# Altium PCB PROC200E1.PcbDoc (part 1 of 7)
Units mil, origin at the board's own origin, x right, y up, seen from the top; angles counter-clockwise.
Board outline 4163.97 x 3505.34 mil, 6 copper layers (Top Layer, GND1, SIG1, PWR, GND2, Bottom), stack 58.132 mil thick; 367 components, 387 nets, 1784 pads, 858 vias.
Unrouted connection lines stored in the file: 17.
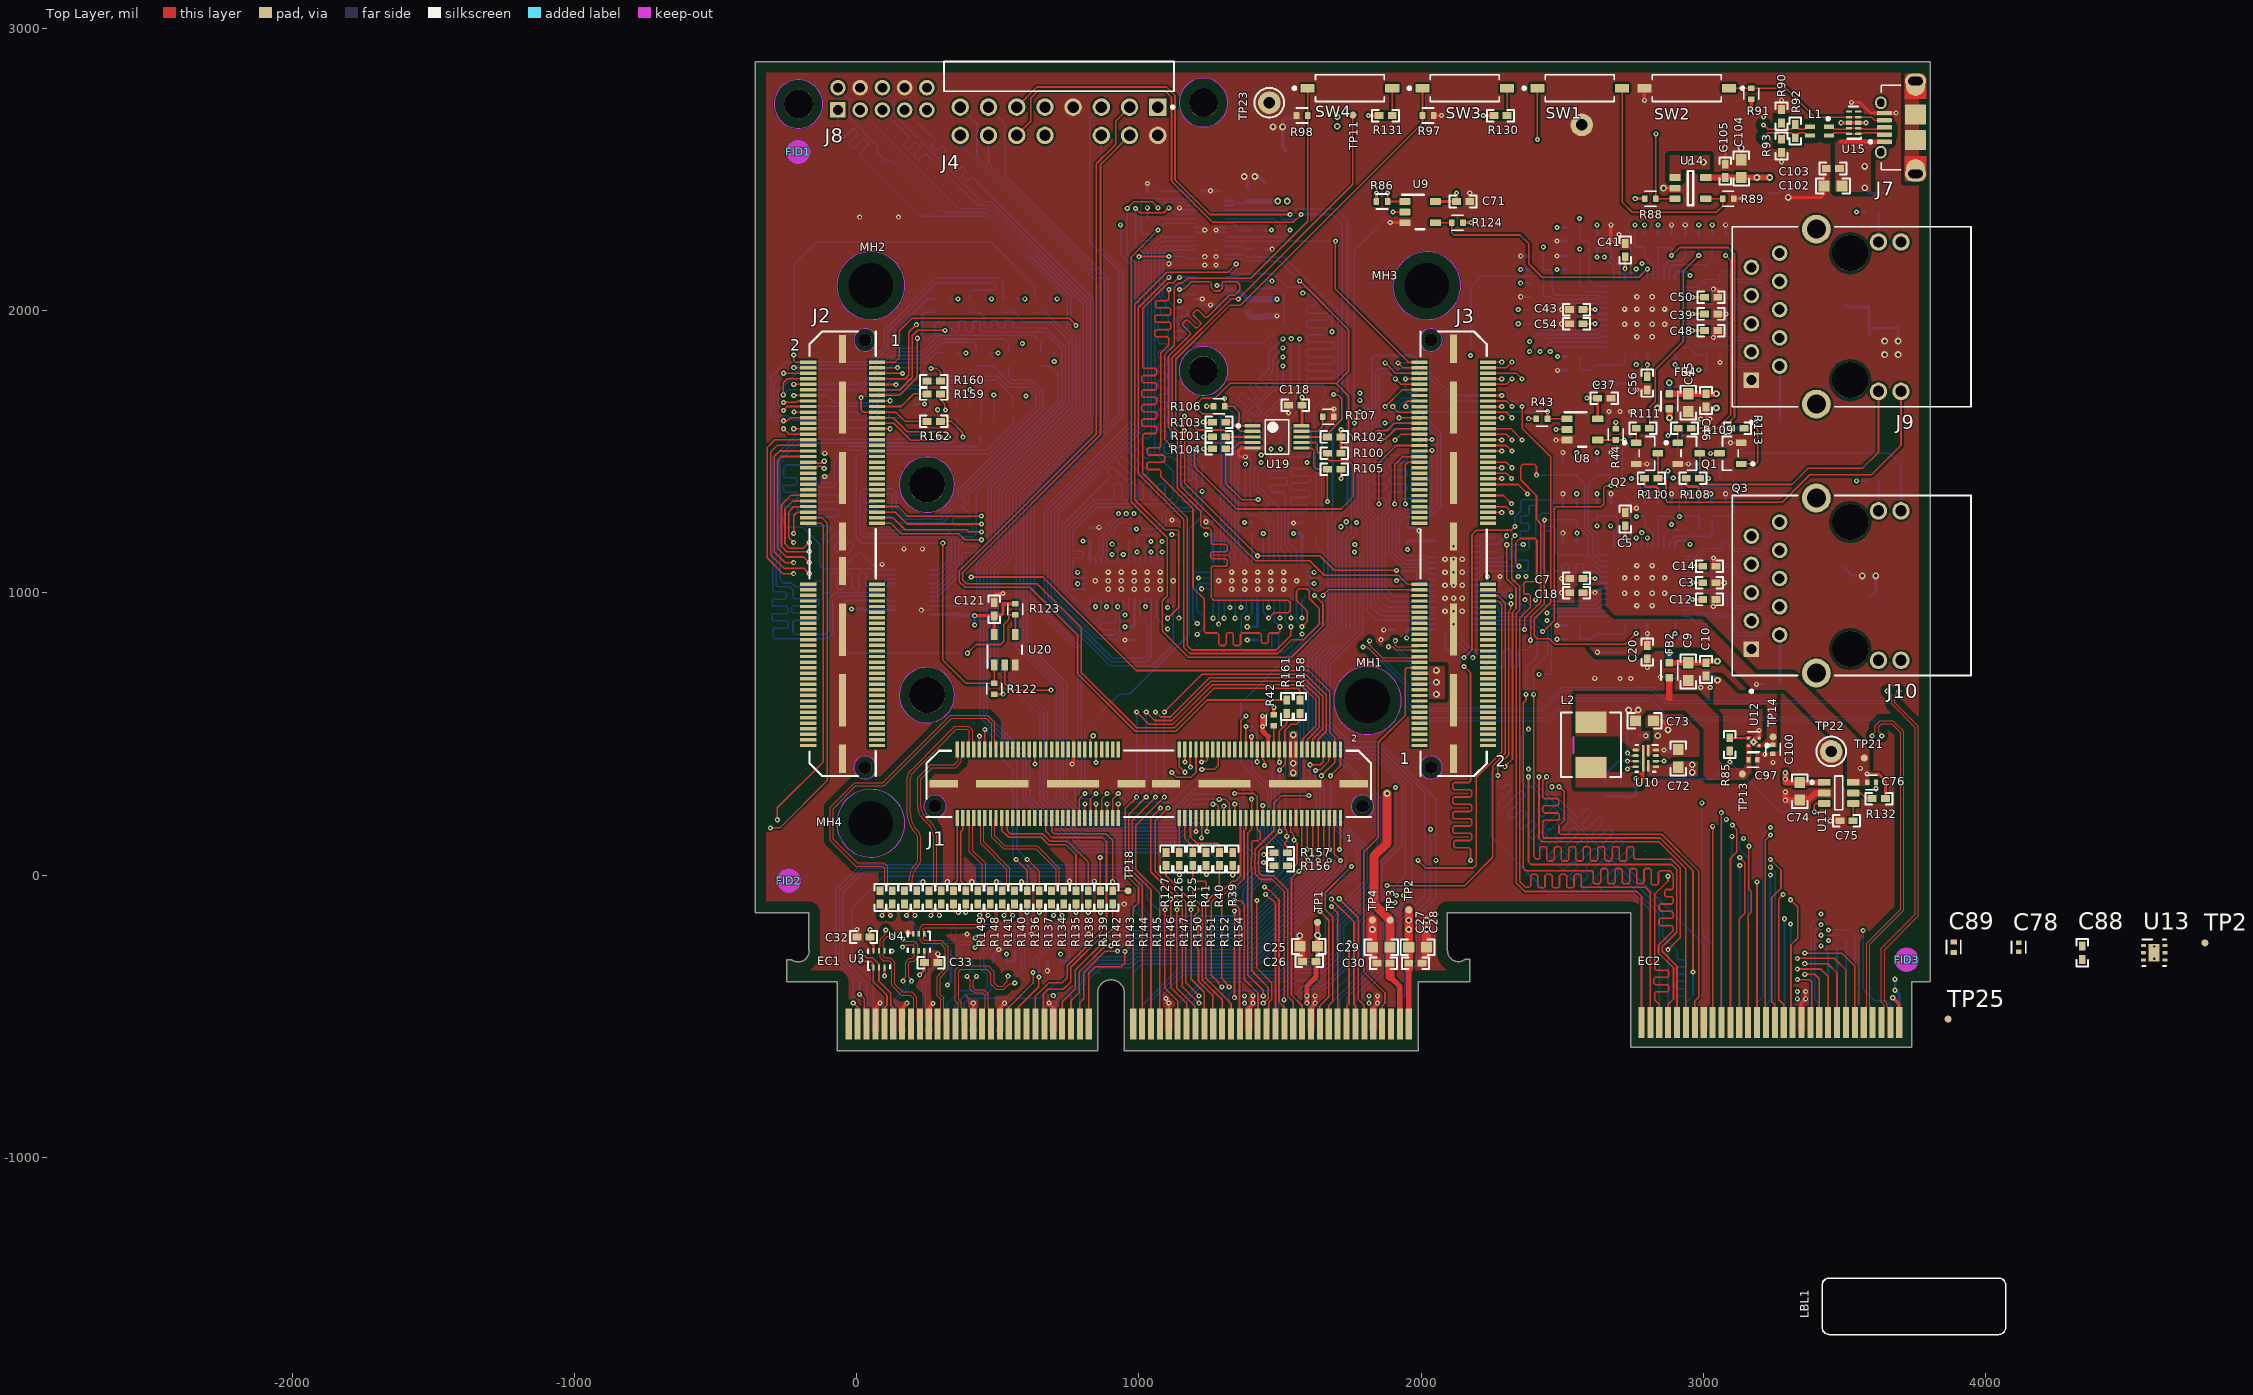
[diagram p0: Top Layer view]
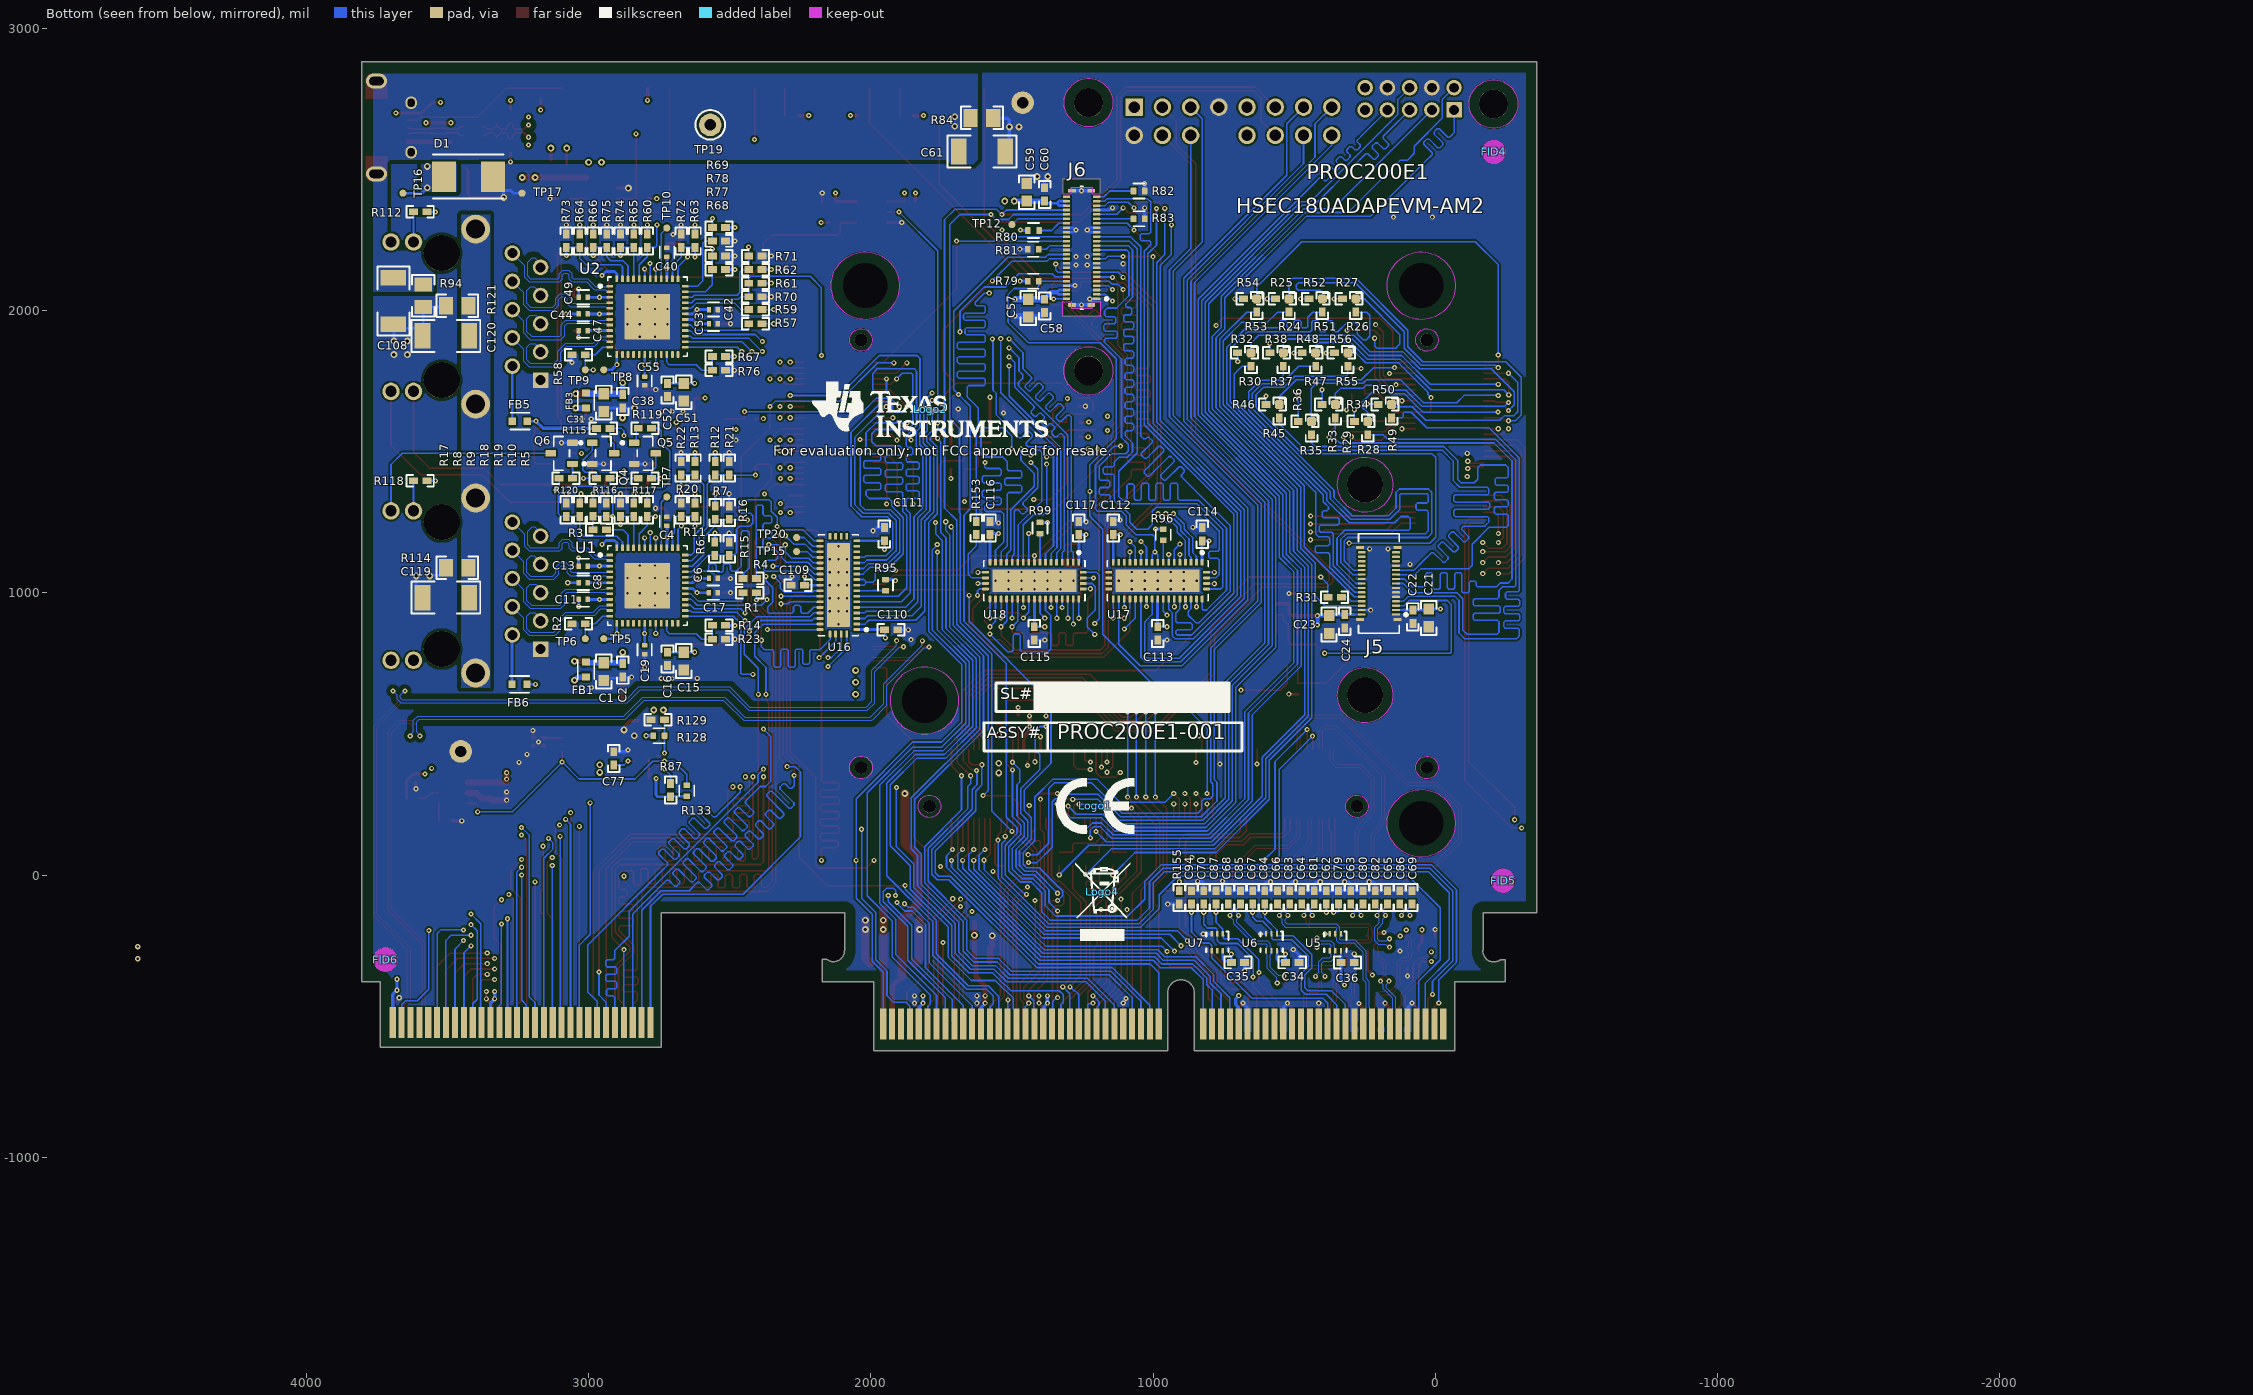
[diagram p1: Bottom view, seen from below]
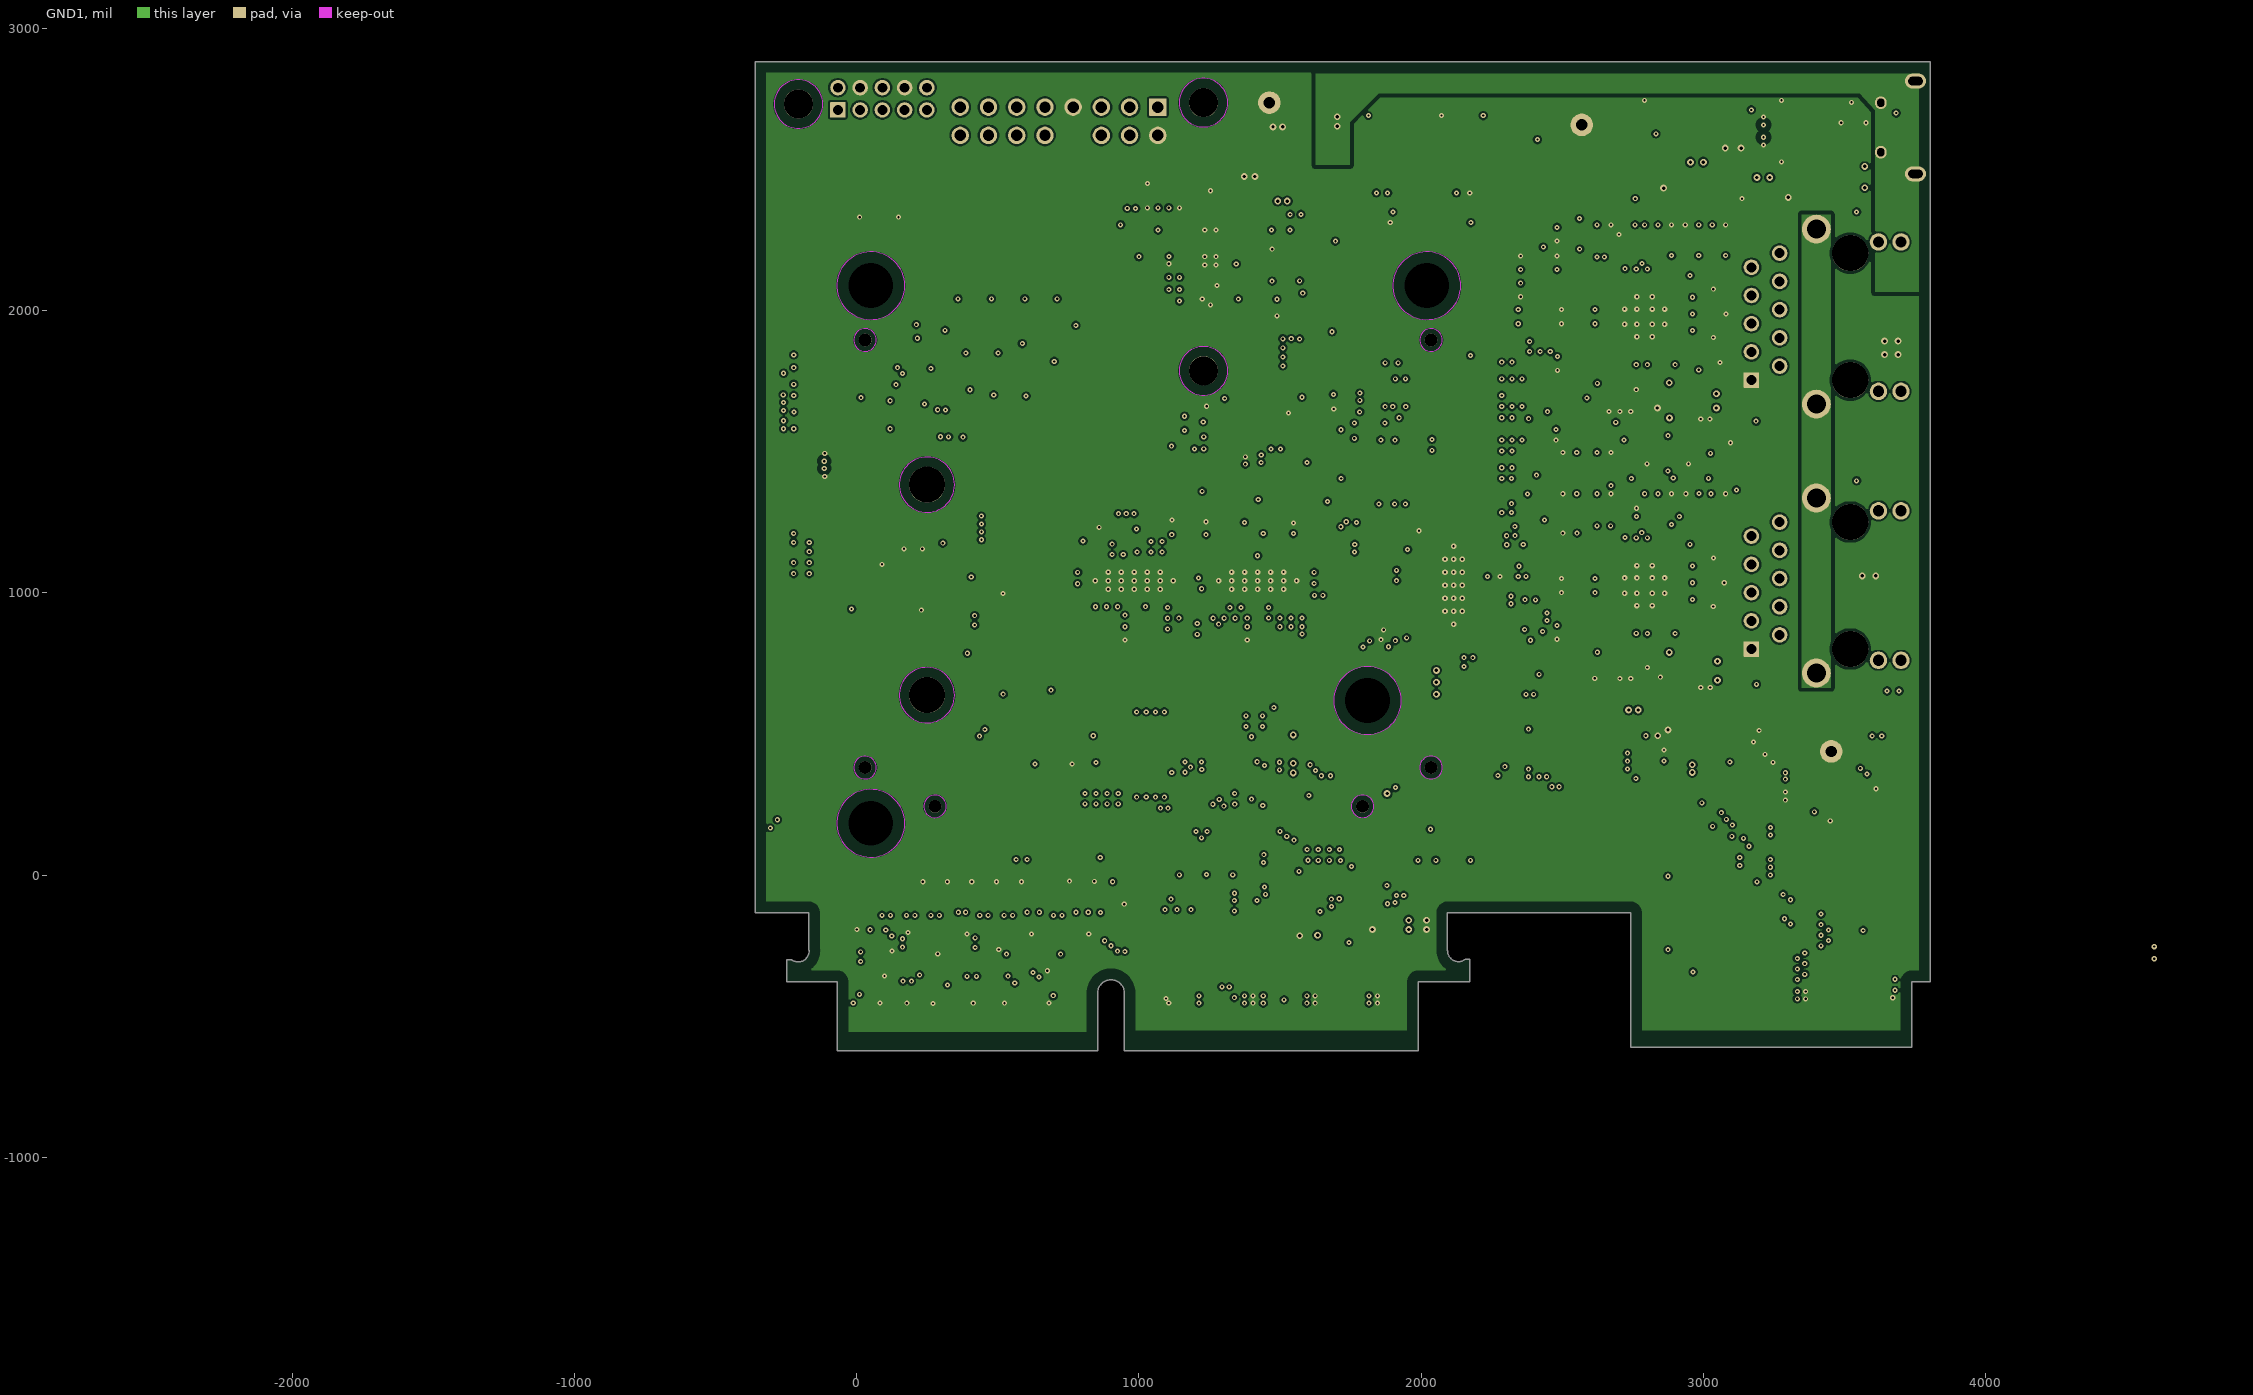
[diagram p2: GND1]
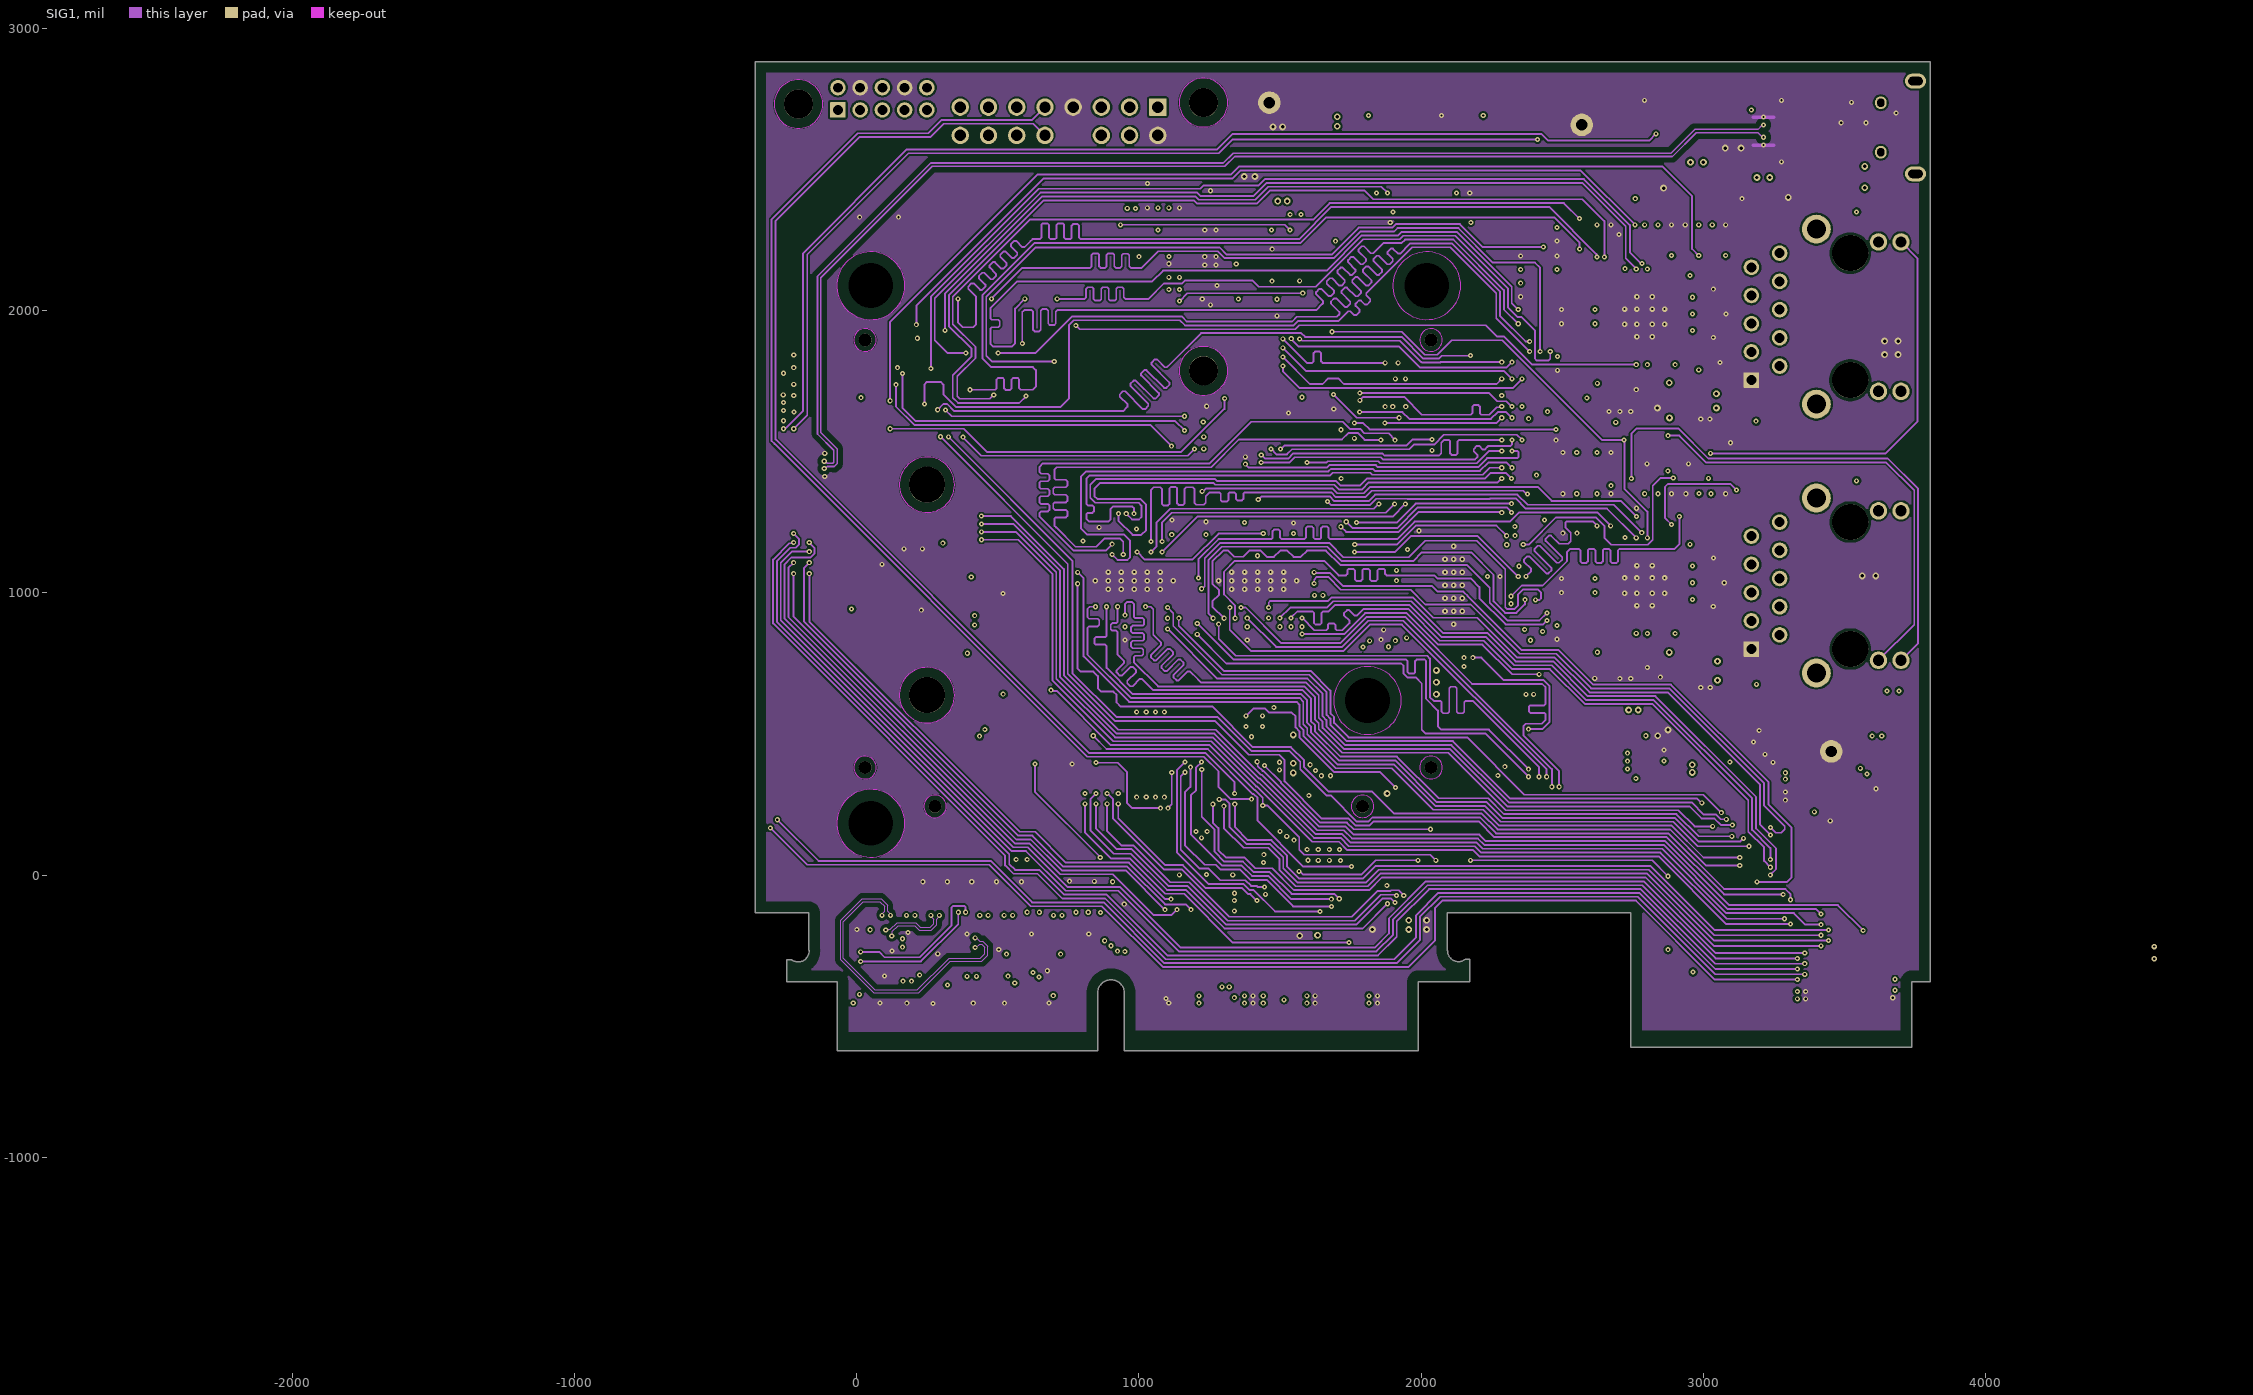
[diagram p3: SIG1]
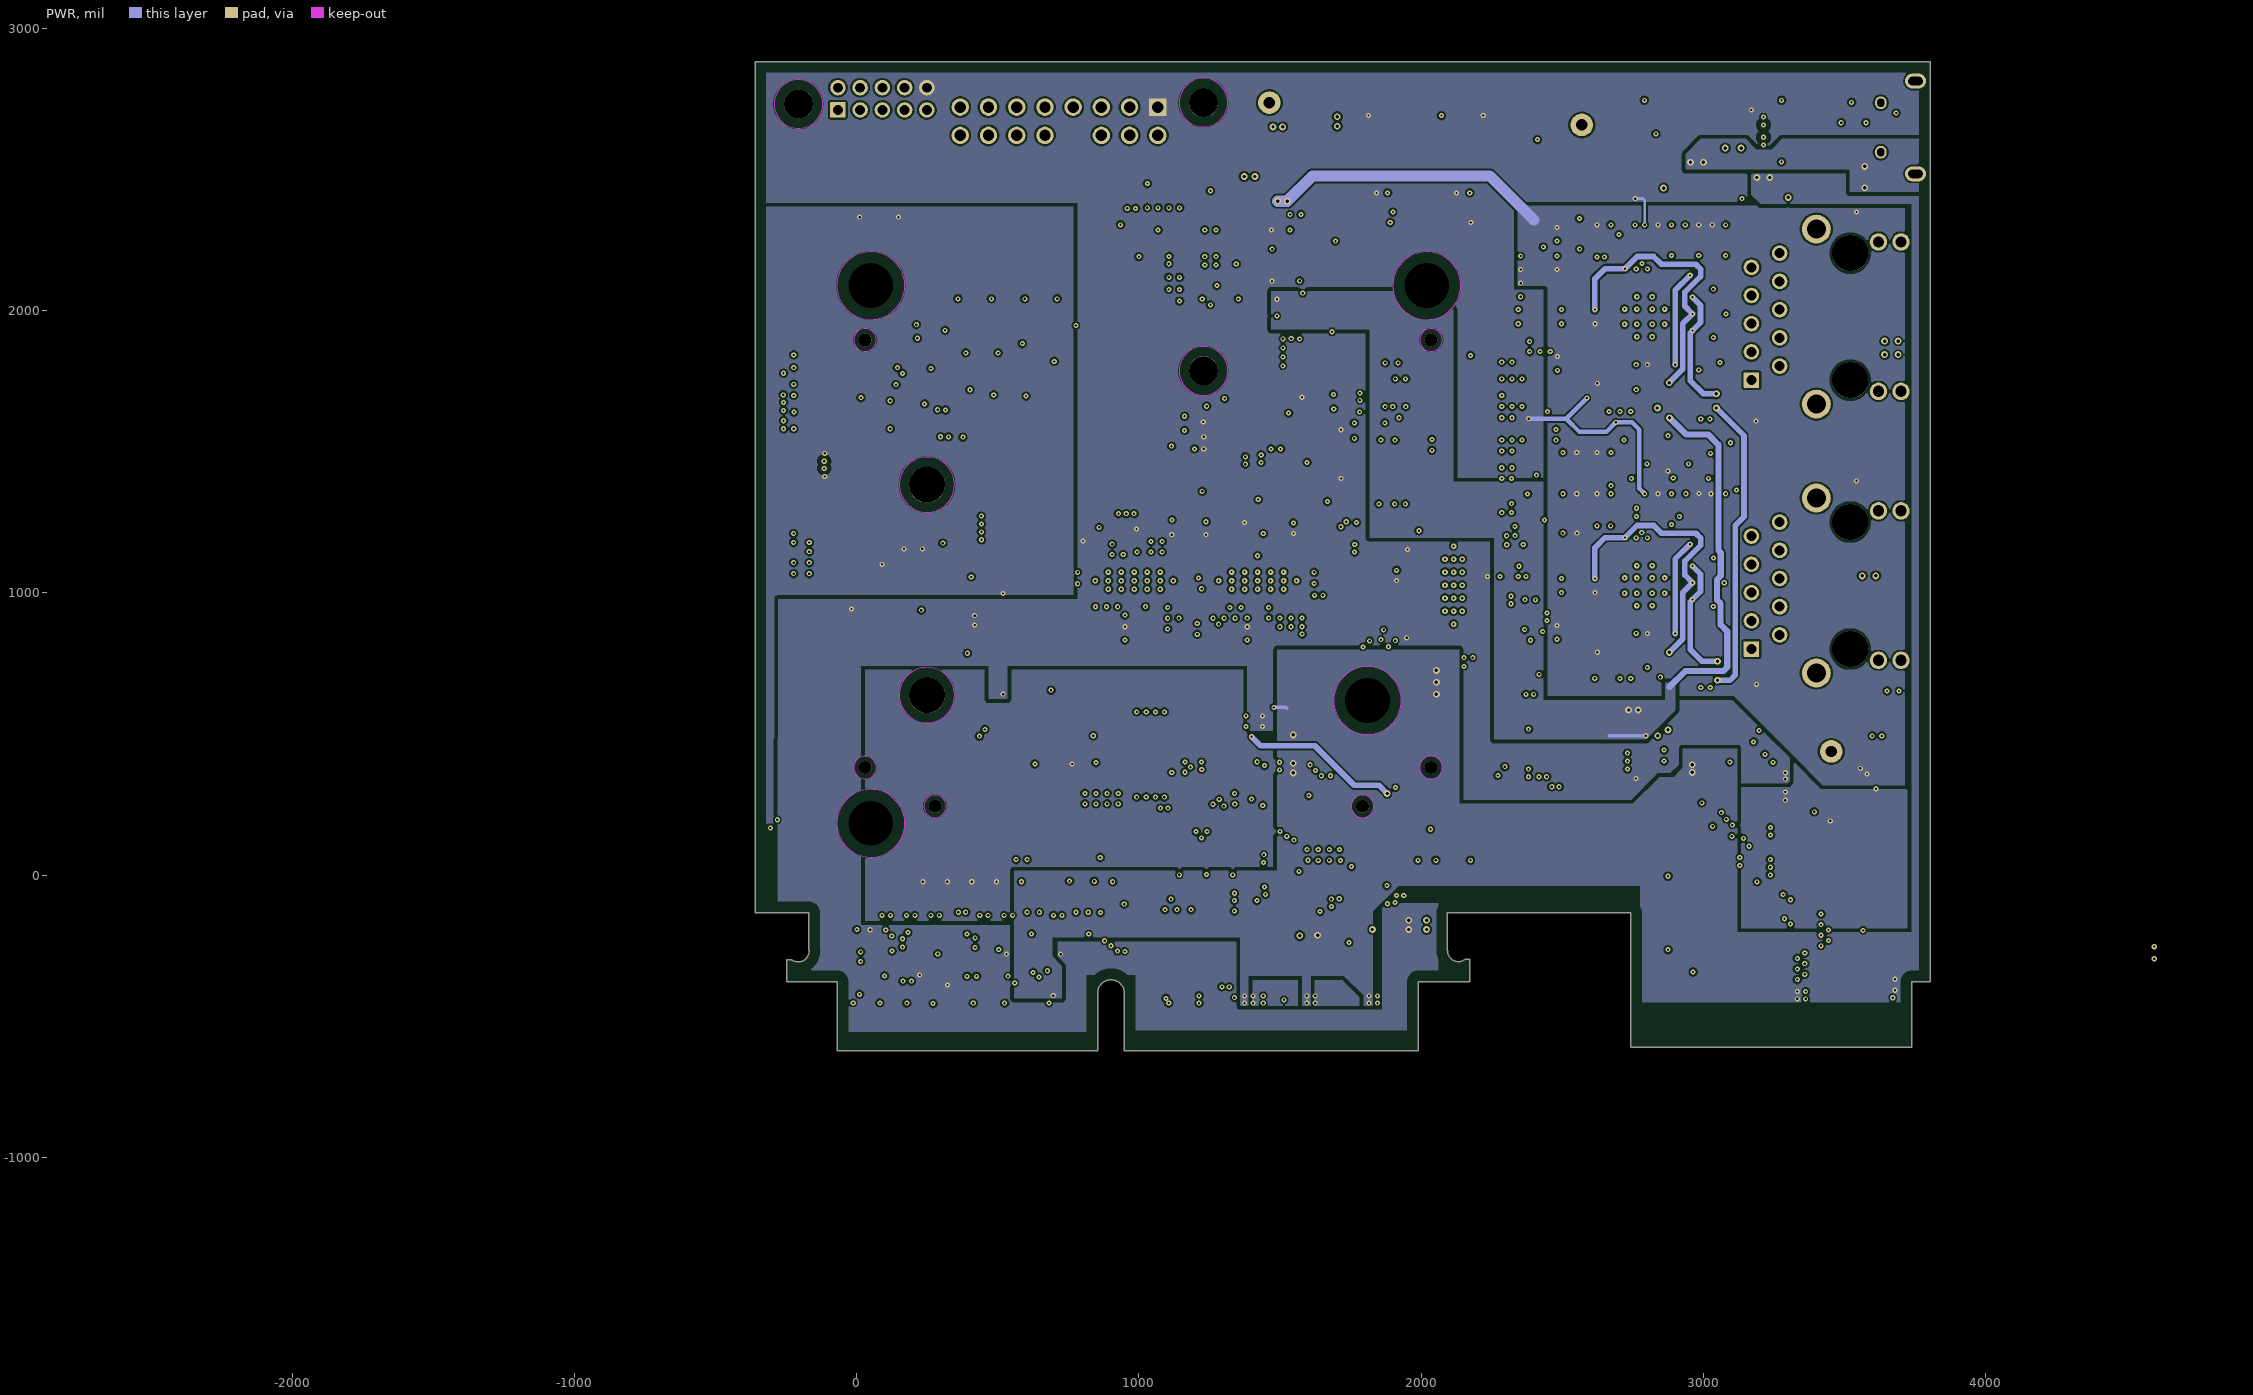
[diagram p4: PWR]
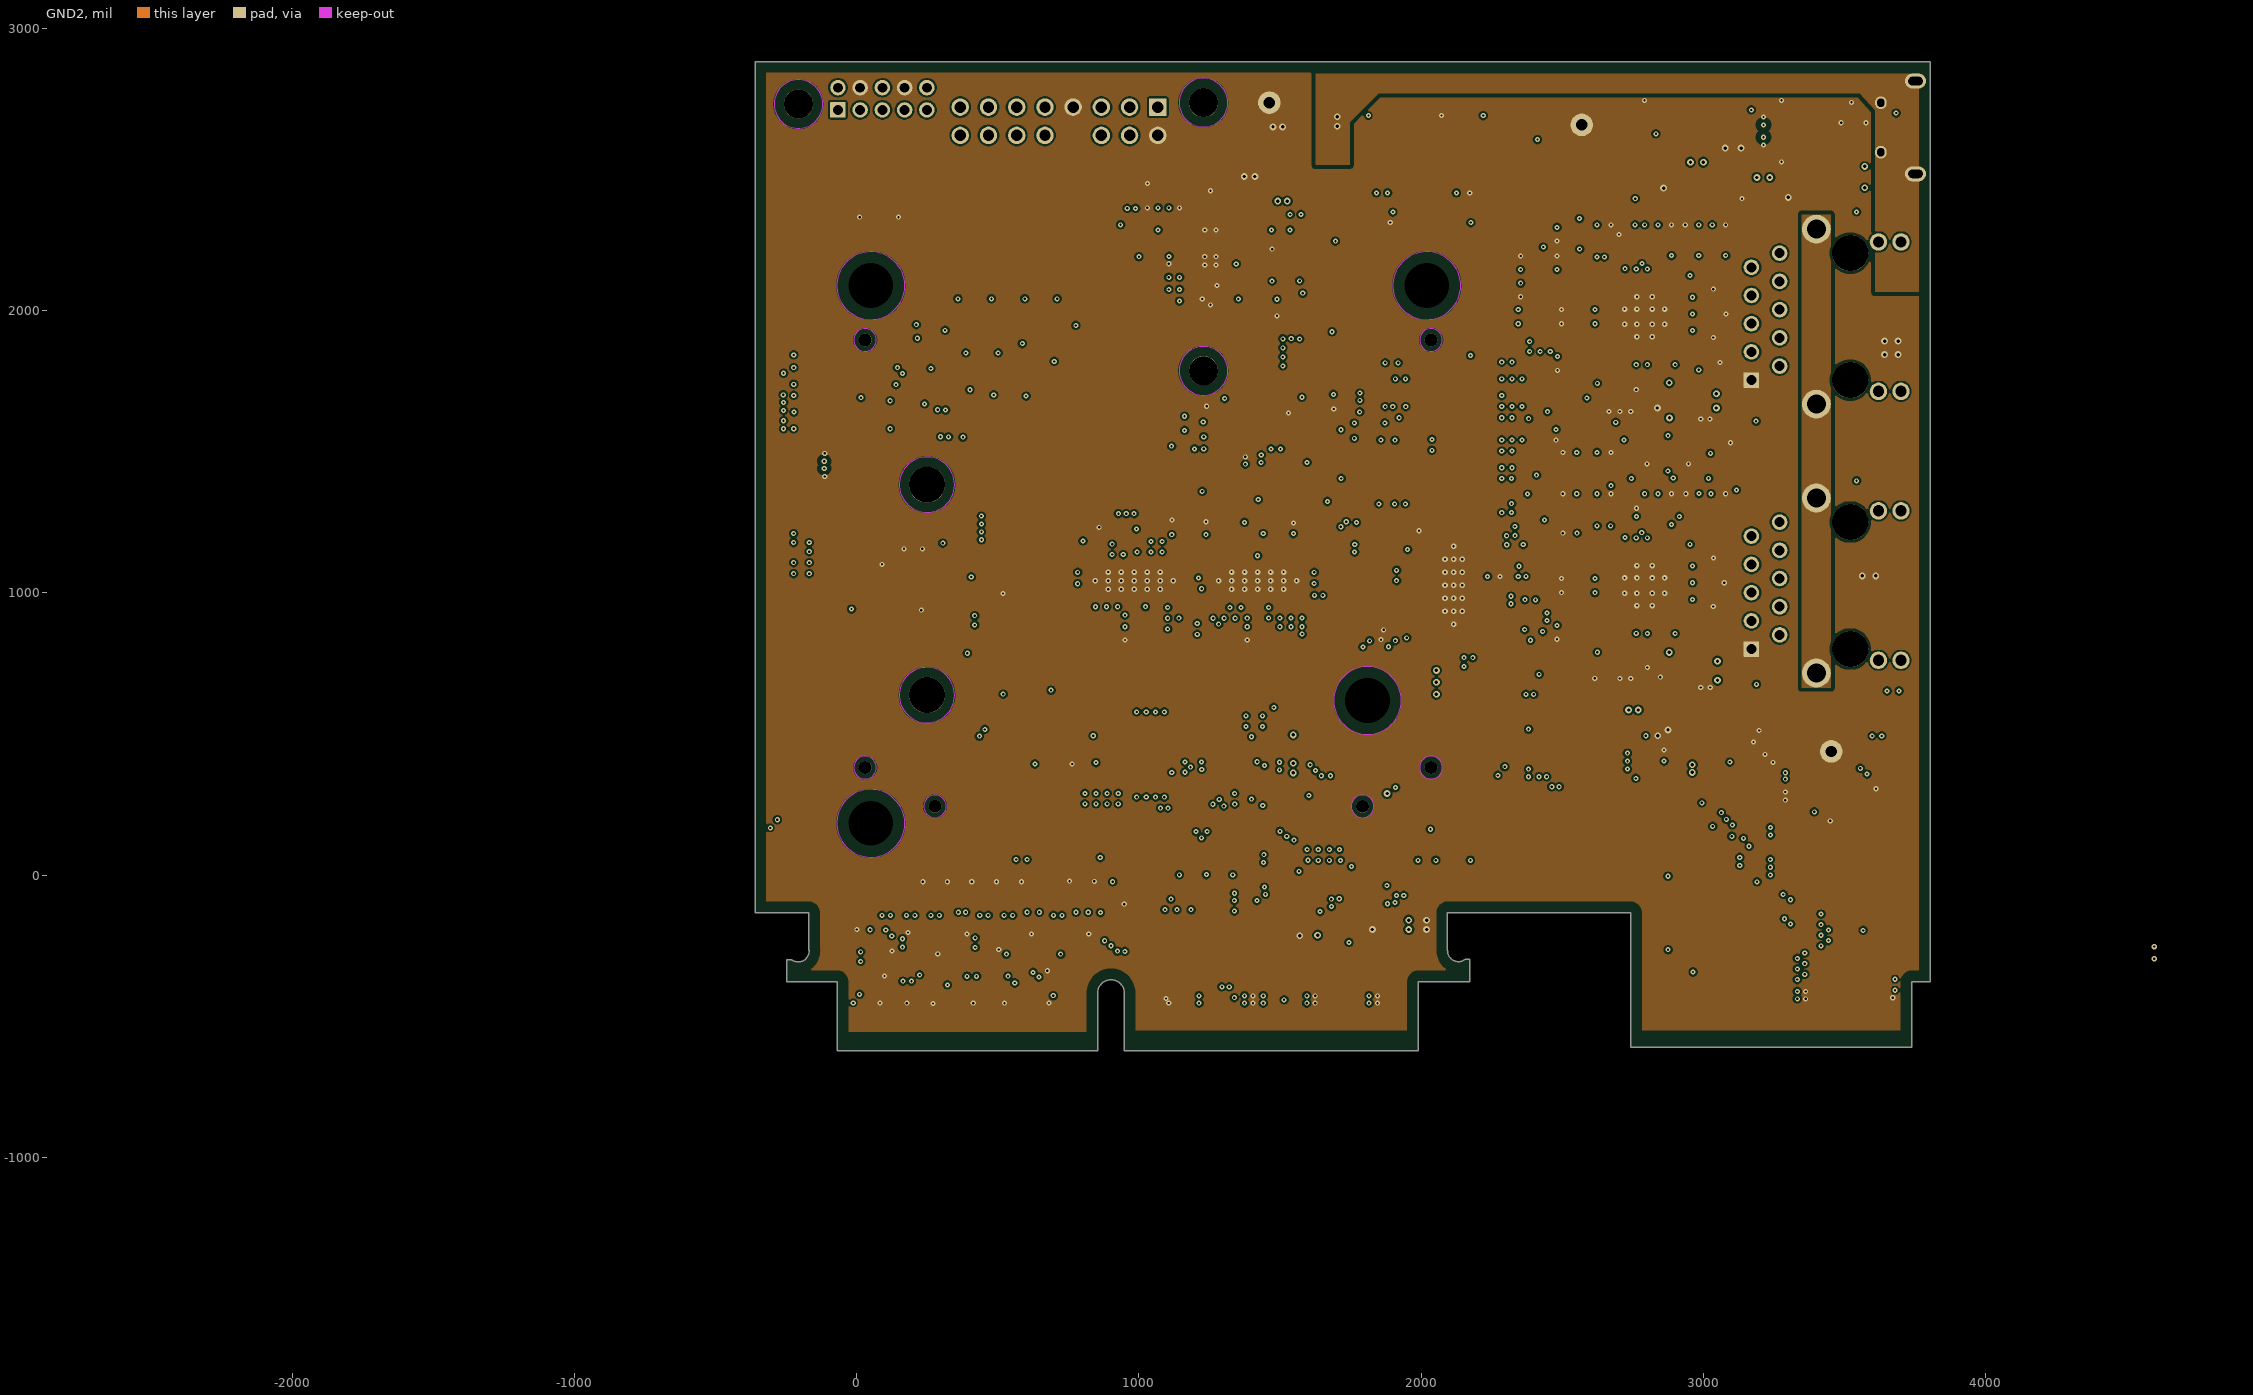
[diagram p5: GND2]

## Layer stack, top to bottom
Top Solder: solder mask 2, Solder Resist, Dk 3.6
Top Layer: signal copper 1.85
Dielectric 1: prepreg 3.696, FR-4, Dk 4.1
GND1: signal copper 1.26
Dielectric 2: core 5, FR-4, Dk 3.7
SIG1: signal copper 1.26
Dielectric 3: prepreg 32, FR-4, Dk 3.7
PWR: signal copper 1.26
Dielectric 4: core 5, FR-4, Dk 3.7
GND2: signal copper 1.26
Dielectric 5: prepreg 3.696, FR-4, Dk 4.1
Bottom: signal copper 1.85
Bottom Solder: solder mask 2, Solder Resist, Dk 3.6

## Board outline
853.8,-622.81 853.8,-418.09 853.9,-418.09 cw(c901.05,-418.09) 948.19,-418.09 948.29,-418.09 948.29,-622.81 1989.24,-622.81 1989.23,-377.97 2171.95,-377.97 2171.95,-298.97 2155.95,-298.97 cw(c2132.45,-267.85) 2093.45,-267.97 2092.95,-267.97 2092.95,-133.97 2743.26,-133.97 2743.26,-609.97 3738.54,-609.97 3738.54,-377.87 3803.95,-377.87 3803.95,2882.53 -360.02,2882.53 -360.02,-133.97 -169.05,-133.97 -169.05,-266.97 -168.55,-266.95 cw(c-207.5,-268.88) -231.05,-299.97 -247.05,-299.97 -247.05,-377.97 -68.64,-377.97 -68.64,-622.81

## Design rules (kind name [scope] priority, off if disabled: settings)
AcuteAngle [All] p1: minimum=4.50000000000000E+0001 checktracksonly=FALSE
AssemblyTestPointUsage [All] p1: valid=2
BoardOutlineClearance [All] p1: gap=40 ignorepadtopadclearanceinfootprint=FALSE
Clearance within_Diff_Pair [InAnyDifferentialPair and WithinRoom('Diff+Pair_Exception_USB_CONN')] p1: gap=4 ignorepadtopadclearanceinfootprint=FALSE except(18.66: Arc-Fill Arc-Poly Arc-Region Track-Fill Track-Poly Track-Region SMDPad-Fill SMDPad-Poly SMDPad-Region THPad-Fill THPad-Poly THPad-Region Via-Fill Via-Poly Via-Region Fill-Fill Fill-Poly Fill-Region Poly-Poly Poly-Region Region-Region)
Clearance Exception_Room [WithinRoom('Diff+Pair_Exception_J2_CONN')] p2: gap=4 ignorepadtopadclearanceinfootprint=FALSE except(15: Arc-Fill Arc-Poly Arc-Region Track-Fill Track-Poly Track-Region SMDPad-Fill SMDPad-Poly SMDPad-Region THPad-Fill THPad-Poly THPad-Region Via-Fill Via-Poly Via-Region Fill-Fill Fill-Poly Fill-Region Poly-Poly Poly-Region Region-Region)
Clearance Footprint_Exception [HasFootprint('DQN0004A-MFG')] p3: gap=4 ignorepadtopadclearanceinfootprint=FALSE except(0: Arc-Hole Track-Hole SMDPad-Hole THPad-Hole Via-Hole Fill-Hole Poly-Hole Region-Hole Text-Hole; 7: Arc-Fill Arc-Poly Track-Fill Track-Poly SMDPad-Fill SMDPad-Poly THPad-Fill THPad-Poly Via-Fill Via-Poly Fill-Fill Fill-Poly Fill-Text Poly-Poly Poly-Region Poly-Text Region-Text Text-Text)
Clearance 90E_3X_EXT [InDifferentialPairClass('DIFF_90E') vs InLayerClass('External Layer')] p4: gap=7 ignorepadtopadclearanceinfootprint=TRUE except(6: Arc-Arc Arc-Track Track-Track; 10: Arc-Hole Track-Hole SMDPad-Hole THPad-Hole Via-Hole Fill-Hole Poly-Hole Region-Hole Text-Hole; 12: Arc-Via Track-Via; 18.66: Arc-THPad Arc-Fill Arc-Poly Arc-Region Track-THPad Track-Fill Track-Poly Track-Region Via-Via Fill-Fill Fill-Poly Fill-Region Poly-Poly Poly-Region Region-Region)
Clearance 90E_3X_INT [InDifferentialPairClass('DIFF_90E') vs OnLayer('SIG1')] p5: gap=7 ignorepadtopadclearanceinfootprint=TRUE except(6: Arc-Arc Arc-Track Track-Track; 10: Arc-Hole Track-Hole SMDPad-Hole THPad-Hole Via-Hole Fill-Hole Poly-Hole Region-Hole Text-Hole; 12: Arc-Via Track-Via Via-Via; 19: Arc-Fill Arc-Poly Arc-Region Track-Fill Track-Poly Track-Region; 20: Arc-SMDPad Arc-THPad Track-SMDPad Track-THPad Fill-Fill Fill-Poly Fill-Region Poly-Poly Poly-Region Region-Region)
Clearance 100E_3X_EXT [InDifferentialPairClass('DIFF_100E') vs InLayerClass('External Layer')] p6: gap=7 ignorepadtopadclearanceinfootprint=TRUE except(6: Arc-Arc Arc-Track Arc-SMDPad Track-Track Track-SMDPad; 8: Arc-THPad Track-THPad; 10: Arc-Hole Track-Hole SMDPad-Hole THPad-Hole Via-Hole Fill-Hole Poly-Hole Region-Hole Text-Hole; 12: Arc-Via Arc-Fill Track-Via Track-Fill Via-Via; 21: Arc-Poly Arc-Region Track-Poly Track-Region Fill-Fill Fill-Poly Fill-Region Poly-Poly Poly-Region Region-Region)
Clearance 100E_3X_INT [InDifferentialPairClass('DIFF_100E') vs OnLayer('SIG1')] p7: gap=7 ignorepadtopadclearanceinfootprint=TRUE except(6: Arc-Arc Arc-Track Track-Track; 10: Arc-Hole Track-Hole SMDPad-Hole THPad-Hole Via-Hole Fill-Hole Poly-Hole Region-Hole Text-Hole; 12: Arc-Via Track-Via Via-Via; 18: Arc-SMDPad Arc-THPad Arc-Fill Arc-Poly Arc-Region Track-SMDPad Track-THPad Track-Fill Track-Poly Track-Region Fill-Fill Fill-Poly Fill-Region Poly-Poly Poly-Region Region-Region)
Clearance Clearance_Keepouts [IsKeepOut] p8: gap=0 ignorepadtopadclearanceinfootprint=FALSE
Clearance [All] p9: gap=7 ignorepadtopadclearanceinfootprint=TRUE except(5.8: Track-THPad; 6: Arc-SMDPad Arc-Via Track-SMDPad Track-Via; 6.6: Track-Track; 8: Via-Via; 10: Arc-Hole Track-Hole SMDPad-Hole THPad-Hole Via-Hole Fill-Hole Poly-Hole Region-Hole Text-Hole; 15: Fill-Fill Fill-Poly Fill-Region Poly-Poly)
ComponentClearance SOM_CONN [HasFootprint('SAMTEC_QTH-060-01-L-D-A') OR InComponentClass('TRIPAD_RES') OR HasFootprint('FP-DF40GB-48DP-0.4V(58)_HDR48-MFG')] p1: gap=0 collisioncheckmode=3 verticalgap=0 showdistances=FALSE
ComponentClearance [All] p2: gap=10 collisioncheckmode=3 verticalgap=10 showdistances=FALSE
DiffPairsRouting DiffPairsRouting_100OHM [InDifferentialPairClass('DIFF_100E')] p1: maxlimit=10 minlimit=6 mostfreqgap=10 toplayer_mingap=7 toplayer_maxgap=7 toplayer_prefgap=7 toplayer_minwidth=4 toplayer_maxwidth=4 toplayer_prefwidth=4 midlayer1_maxgap=6 midlayer1_prefgap=6 midlayer1_minwidth=4.2 midlayer1_maxwidth=4.2 midlayer1_prefwidth=4.2 midlayer4_maxgap=6 midlayer4_prefgap=6 midlayer4_minwidth=4.2 midlayer4_maxwidth=4.2 midlayer4_prefwidth=4.2 bottomlayer_mingap=7 bottomlayer_maxgap=7 bottomlayer_prefgap=7 bottomlayer_minwidth=4 bottomlayer_maxwidth=4 bottomlayer_prefwidth=4 impedanceprofiledriven=TRUE impedanceprofileid={A94D5FAB-CF00-4FEB-BD54-E9BDB7478A9D} impedanceprofilevalue=100.000000 maxuncoupledlength=600
DiffPairsRouting DiffPairsRouting_90OHM [InDifferentialPairClass('DIFF_90E')] p2: maxlimit=10 minlimit=6 mostfreqgap=10 toplayer_mingap=6.22 toplayer_maxgap=6.22 toplayer_prefgap=6.22 toplayer_minwidth=5 toplayer_maxwidth=5 toplayer_prefwidth=5 midlayer1_maxgap=6 midlayer1_prefgap=6 midlayer1_minwidth=5.7 midlayer1_maxwidth=5.7 midlayer1_prefwidth=5.7 midlayer4_maxgap=6 midlayer4_prefgap=6 midlayer4_minwidth=5.7 midlayer4_maxwidth=5.7 midlayer4_prefwidth=5.7 bottomlayer_mingap=6.22 bottomlayer_maxgap=6.22 bottomlayer_prefgap=6.22 bottomlayer_minwidth=5 bottomlayer_maxwidth=5 bottomlayer_prefwidth=5 impedanceprofiledriven=TRUE impedanceprofileid={C7C87971-DC9D-4F38-B813-0A1832E5FAEC} impedanceprofilevalue=90.000000 maxuncoupledlength=500
FabricationTestPointUsage TestPointUsage [All] p1: valid=2 allowmultiple=FALSE
FabricationTestpoint Testpoint [All] p1: side=3 testpointundercomponent=TRUE minsize=40 maxsize=100 preferedsize=60 minholesize=0 maxholesize=40 preferedholesize=32 testpointgrid=1 allowsidetop=TRUE allowsidebottom=TRUE usegrid=TRUE gridtolerance=0.01
FanoutControl Fanout_LCC [IsLCC] p1: bgadir=Out bgaviamode=Centered fanoutstyle=Auto fanoutdirection=Alternating viagrid=1 // Fanout_LCC (Default Rule)
FanoutControl Fanout_BGA [IsBGA] p2: bgadir=Out bgaviamode=Centered fanoutstyle=Auto fanoutdirection=Alternating viagrid=1 // Fanout_BGA (Default Rule)
FanoutControl Fanout_Default [All] p4: bgadir=Out bgaviamode=Centered fanoutstyle=Auto fanoutdirection=Alternating viagrid=1 // Fanout_Default (Default Rule)
FanoutControl Fanout_Small [(CompPinCount < 5)] p5: bgadir=Out bgaviamode=Centered fanoutstyle=Auto fanoutdirection=OutThenIn viagrid=1 // Fanout_Small (Default Rule)
Height Under_SOM [WithinRoom('SOM_HeightRestriction')] p1: minheight=0 maxheight=118.11 prefheight=78.74
Height [All] p2: minheight=0 maxheight=1000 prefheight=500
HoleSize [All] p1: absolutevalues=TRUE maxlimit=500 minlimit=7.87 maxpercent=80.000 minpercent=20.000
HoleToHoleClearance [All] p1: gap=9 allowstackedmicrovias=TRUE
MatchedLengths MII1_TX_GRP1 [InxSignalClass('MII1_TX_GRP1')] p1: tolerance=10 checknetsindiffpair=FALSE checkdiffpairvsdiffpair=TRUE checkxsignals=TRUE checkothers=TRUE
MatchedLengths MII1_TX_GRP2 [InxSignalClass('MII1_TX_GRP2')] p2: tolerance=10 checknetsindiffpair=FALSE checkdiffpairvsdiffpair=TRUE checkxsignals=TRUE checkothers=TRUE targetsourcename=ICSSM_MII1_TXCLK-NetR153_1_PP1
MatchedLengths MII1_RX_GRP1 [InxSignalClass('MII1_RX_GRP1')] p3: tolerance=10 checknetsindiffpair=FALSE checkdiffpairvsdiffpair=TRUE checkxsignals=TRUE checkothers=TRUE
MatchedLengths MII1_RX_GRP2 [InxSignalClass('MII1_RX_GRP2')] p4: tolerance=10 checknetsindiffpair=FALSE checkdiffpairvsdiffpair=TRUE checkxsignals=TRUE checkothers=TRUE targetsourcename=ICSSM_MII1_RXCLK_PP1
MatchedLengths FSI_HDR_RX [InxSignalClass('FSI_HDR_RX')] p5: tolerance=10 checknetsindiffpair=FALSE checkdiffpairvsdiffpair=TRUE checkxsignals=TRUE checkothers=TRUE
MatchedLengths FSI_HDR_TX [InxSignalClass('FSI_HDR_TX')] p6: tolerance=10 checknetsindiffpair=FALSE checkdiffpairvsdiffpair=TRUE checkxsignals=TRUE checkothers=TRUE targetsourcename=AM26x_FSITX0_CLK_PP1
MatchedLengths FSI_HSEC_RX [InxSignalClass('FSI_HSEC_RX')] p7: tolerance=10 checknetsindiffpair=FALSE checkdiffpairvsdiffpair=TRUE checkxsignals=TRUE checkothers=TRUE targetsourcename=AM26x_FSIRX0_CLK-HSEC_FSIRX0_CLK_PP1
MatchedLengths MII0_HSEC_RX_GRP1 [InxSignalClass('MII0_HSEC_RX_GRP1')] p8: tolerance=10 checknetsindiffpair=FALSE checkdiffpairvsdiffpair=TRUE checkxsignals=TRUE checkothers=TRUE
MatchedLengths MII0_HSEC_RX_GRP2 [InxSignalClass('MII0_HSEC_RX_GRP2')] p9: tolerance=10 checknetsindiffpair=FALSE checkdiffpairvsdiffpair=TRUE checkxsignals=TRUE checkothers=TRUE targetsourcename=HSEC_ICSSM_MII0_RXCLK_PP1
MatchedLengths MII0_HSEC_TX_GRP1 [InxSignalClass('MII0_HSEC_TX_GRP1')] p10: tolerance=10 checknetsindiffpair=FALSE checkdiffpairvsdiffpair=TRUE checkxsignals=TRUE checkothers=TRUE
MatchedLengths MII0_HSEC_TX_GRP2 [InxSignalClass('MII0_HSEC_TX_GRP2')] p11: tolerance=10 checknetsindiffpair=FALSE checkdiffpairvsdiffpair=TRUE checkxsignals=TRUE checkothers=TRUE targetsourcename=HSEC_ICSSM_MII0_TXCLK_PP1
MatchedLengths MII0_TX_GRP1 [InxSignalClass('MII0_TX_GRP1')] p12: tolerance=10 checknetsindiffpair=FALSE checkdiffpairvsdiffpair=TRUE checkxsignals=TRUE checkothers=TRUE
MatchedLengths MII0_TX_GRP2 [InxSignalClass('MII0_TX_GRP2')] p13: tolerance=10 checknetsindiffpair=FALSE checkdiffpairvsdiffpair=TRUE checkxsignals=TRUE checkothers=TRUE targetsourcename=ICSSM_MII0_TXCLK-R_ICSSM_MII0_TXCLK_PP1
MatchedLengths MII0_RX_GRP1 [InxSignalClass('MII0_RX_GRP1')] p14: tolerance=10 checknetsindiffpair=FALSE checkdiffpairvsdiffpair=TRUE checkxsignals=TRUE checkothers=TRUE
MatchedLengths MII0_RX_GRP2 [InxSignalClass('MII0_RX_GRP2')] p15: tolerance=10 checknetsindiffpair=FALSE checkdiffpairvsdiffpair=TRUE checkxsignals=TRUE checkothers=TRUE targetsourcename=ICSSM_MII0_RXCLK-R_ICSSM_MII0_RXCLK_PP1
MatchedLengths MII1_HSEC_TX_GRP1 [InxSignalClass('MII1_HSEC_TX_GRP1')] p16: tolerance=10 checknetsindiffpair=FALSE checkdiffpairvsdiffpair=TRUE checkxsignals=TRUE checkothers=TRUE
MatchedLengths MII1_HSEC_TX_GRP2 [InxSignalClass('MII1_HSEC_TX_GRP2')] p17: tolerance=10 checknetsindiffpair=FALSE checkdiffpairvsdiffpair=TRUE checkxsignals=TRUE checkothers=TRUE targetsourcename=HSEC_ICSSM_MII1_TXCLK_PP1
MatchedLengths MII1_HSEC_RX_GRP1 [InxSignalClass('MII1_HSEC_RX_GRP1')] p18: tolerance=10 checknetsindiffpair=FALSE checkdiffpairvsdiffpair=TRUE checkxsignals=TRUE checkothers=TRUE
MatchedLengths MII1_HSEC_RX_GRP2 [InxSignalClass('MII1_HSEC_RX_GRP2')] p19: tolerance=10 checknetsindiffpair=FALSE checkdiffpairvsdiffpair=TRUE checkxsignals=TRUE checkothers=TRUE targetsourcename=HSEC_ICSSM_MII1_RXCLK_PP1
MatchedLengths OSPI_Group [InxSignalClass('J2_OSPI_CONN')] p20: tolerance=10 checknetsindiffpair=FALSE checkdiffpairvsdiffpair=TRUE checkxsignals=TRUE checkothers=TRUE targetsourcename=CONN_OSPI1_CLK-RGMII1_RXC_PP1
MatchedLengths RGMII1_RX_GRP [InxSignalClass('J2_RGMII1_RX_GRP')] p21: tolerance=10 checknetsindiffpair=FALSE checkdiffpairvsdiffpair=TRUE checkxsignals=TRUE checkothers=TRUE
MatchedLengths RGMII1_TX_GRP [InxSignalClass('J2_RGMII1_TX_GRP')] p22: tolerance=10 checknetsindiffpair=FALSE checkdiffpairvsdiffpair=TRUE checkxsignals=TRUE checkothers=TRUE
MatchedLengths PHY1_GrpMatch [InxSignalClass('PHY1_U2')] p23: tolerance=10 checknetsindiffpair=FALSE checkdiffpairvsdiffpair=TRUE checkxsignals=TRUE checkothers=TRUE
MatchedLengths PHY2_GrpMatch [InxSignalClass('PHY2_U1')] p24: tolerance=10 checknetsindiffpair=FALSE checkdiffpairvsdiffpair=TRUE checkxsignals=TRUE checkothers=TRUE
MatchedLengths Diff_pairs [InAnyDifferentialPair] p25: tolerance=2 checknetsindiffpair=TRUE checkdiffpairvsdiffpair=FALSE checkxsignals=FALSE checkothers=FALSE
MinimumAnnularRing [All] p1: minimumring=5
MinimumSolderMaskSliver [All] p1: minsoldermaskwidth=6
PlaneClearance [All] p1: clearance=10
PlaneConnect [All] p1: planeconnectstyle=Direct reliefexpansion=10 reliefentries=4 reliefconductorwidth=10 reliefairgap=10
PolygonConnect [All] p1: connectstyle=Direct reliefconductorwidth=10 reliefentries=4 polygonreliefangle="90 Angle" airgapwidth=10
RoomDefinition Diff+Pair_Exception_J2_CONN [False vs False] p1: confinementstyle=ConfineIn formatcopy=TRUE lockcomponents=FALSE outline -319.67,1532.92 -74.89,1532.92 -74.89,1386.11 -319.67,1386.11
RoomDefinition Diff+Pair_Exception_USB_CONN [False vs False] p2: confinementstyle=ConfineIn formatcopy=TRUE lockcomponents=FALSE outline 3015,2855 3803.95,2855 3803.95,2386.29 3015,2386.29
RoomDefinition SOM_HeightRestriction [False vs False] p3: confinementstyle=ConfineIn formatcopy=TRUE lockcomponents=FALSE outline -360.02,2366.03 2750.22,2366.03 2750.22,-133.97 -360.02,-133.97
RoutingLayers [All] p1: top layer_v5=TRUE mid layer 1_v5=TRUE mid layer 2_v5=FALSE mid layer 3_v5=FALSE mid layer 4_v5=TRUE bottom layer_v5=TRUE
RoutingVias [All] p1: holewidth=8 width=22 viastyle="Through Hole" minholewidth=7.87 minwidth=18 maxholewidth=8 maxwidth=22 useviatemplates=TRUE viatemplateguid#1={BFC155CB-09EB-4870-8CCE-6FF5007BB52B} viatemplateguid#2={C4D4361A-8B44-4329-B568-289A0E0AE5F7} viatemplateguid#3={A6E074F1-B809-4F0C-AFE9-9FFF64B6E93D} viatemplatename#1=v46h20m0mx0(Tol8-8) viatemplatename#2=v50h20m50 viatemplatename#3=v61h30m0mx0(Tol8-8)
SilkToBoardRegionClearance [Not ((IsComment or IsDesignator) And (Hide <> 'False')) and not InRegion(1000,500,4000,800)] p1:
SilkToSilkClearance [All] p1: silktosilkclearance=4
SilkToSolderMaskClearance "Silk to Solder Mask Opening" [all] p1: minsilkscreentomaskgap=4 clearancetoexposedcopper=FALSE
SolderMaskExpansion [All] p1: expansion=1.97 istentingtop=FALSE
UnRoutedNet [All] p1: checkbadconnections=TRUE
Width Width_PWR [InNetClass('POWER')] p1: maxlimit=40 minlimit=7.89 preferedwidth=14
Width [InNetClass('All Nets')] p2: maxlimit=40 minlimit=5.66 preferedwidth=6.66 toplayer_maxwidth=10 toplayer_prefwidth=5.66 midlayer1_minwidth=6.66 midlayer1_maxwidth=10 midlayer2_minwidth=10 midlayer2_prefwidth=20 midlayer3_minwidth=10 midlayer3_prefwidth=20 midlayer4_minwidth=6.66 midlayer4_maxwidth=10 bottomlayer_maxwidth=10 bottomlayer_prefwidth=5.66 minimp=50.000000 maximp=50.000000 favimp=50.000000 checkconnectedcopper=TRUE
10 further rules are at their usual default settings.

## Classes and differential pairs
component class TRIPAD_RES: R24 R25 R26 R27 R28 R29 R30 R32 R33 R34 R35 R36 R37 R38 R45 R46 R47 R48 R49 R50 R51 R52 R53 R54 R55 R56
differential pair class DIFF_90E: AM26x_USB0 USBMICROAB
differential pair class HSEC_ADC: HSEC_ADC0_AIN_2_3 HSEC_ADC0_AIN_4_5 HSEC_ADC1_AIN_0_1 HSEC_ADC1_AIN_2_3 HSEC_ADC2_AIN_0_1 HSEC_ADC2_AIN_2_3
differential pair class DIFF_100E: AM26x_ADC0_AIN_2_3 AM26x_ADC0_AIN_4_5 AM26x_ADC1_AIN_0_1 AM26x_ADC1_AIN_2_3 AM26x_ADC2_AIN_0_1 AM26x_ADC2_AIN_2_3 HSEC_ADC0_AIN_2_3 HSEC_ADC0_AIN_4_5 HSEC_ADC1_AIN_0_1 HSEC_ADC1_AIN_2_3 HSEC_ADC2_AIN_0_1 HSEC_ADC2_AIN_2_3 PMIC_COMP1 PMIC_COMP2 RJ45_ETH1_D0 RJ45_ETH1_D1 RJ45_ETH1_D2 RJ45_ETH1_D3 RJ45_ETH2_D0 RJ45_ETH2_D1 RJ45_ETH2_D2 RJ45_ETH2_D3
differential pair class AM26x_ADC: AM26x_ADC0_AIN_2_3 AM26x_ADC0_AIN_4_5 AM26x_ADC1_AIN_0_1 AM26x_ADC1_AIN_2_3 AM26x_ADC2_AIN_0_1 AM26x_ADC2_AIN_2_3
differential pair class PMIC_COMP: PMIC_COMP1 PMIC_COMP2
differential pair class RJ45_ETH2: RJ45_ETH2_D0 RJ45_ETH2_D1 RJ45_ETH2_D2 RJ45_ETH2_D3
differential pair class RJ45_ETH1: RJ45_ETH1_D0 RJ45_ETH1_D1 RJ45_ETH1_D2 RJ45_ETH1_D3
net class POWER: 3V3_LDO2 5V0_LDO3 GND RJ45_1_VCC RJ45_2_VCC SHIELD2 SHIELD5 VBUS_MICRO_AB_5V0 VDD_ETH1_1V1_PHY VDD_ETH1_2V5_PHY VDD_ETH2_1V1_PHY VDD_ETH2_2V5_PHY VDD_ETH_1V1 VDD_ETH_2V5 VDDA1_1V8 VDDA2_1V8 VDDIO_3V3 VMAIN_5V0_IN
component class PROC200_RJ45_1_2: C119 C120 FB5 FB6 J9 J10 Q1 Q2 Q3 Q4 Q5 Q6 R108 R109 R110 R111 R112 R113 R114 R115 R116 R117 R118 R119 R120 R121
component class PROC200_PHY_MUX: C109 C110 C111 C112 C113 C114 C115 C116 C117 C118 R95 R96 R97 R98 R99 R100 R101 R102 R103 R104 R105 R106 R107 R130 R131 R153 SW3 SW4 TP15 TP20 U16 U17 U18 U19
component class "PROC200_OSPI_FSI _DAC_Emmulator_Header": C21 C22 C23 C24 C78 C88 C89 C121 J4 J5 J8 R24 R25 R26 R27 R28 R29 R30 R31 R32 R33 R34 R35 R36 R37 R38 R45 R46 R47 R48 R49 R50 R51 R52 R53 R54 R55 R56 R122 R123 TP24 U13 U20
component class PROC200_MII1_ADD_ON_CONN: C57 C58 C59 C60 C61 J6 R79 R80 R81 R82 R83 R84 TP11 TP12
component class PROC200_LDO_USB_MICRO-AB: C72 C73 C74 C75 C76 C77 C97 C100 C102 C103 C104 C105 C108 D1 J7 L1 L2 R85 R87 R88 R89 R90 R91 R92 R93 R94 R128 R129 R132 R133 SW1 SW2 TP13 TP14 TP16 TP17 TP21 TP22 TP23 U10 U11 U12 U14 U15
component class PROC200_High_Density_conn3: J3
component class PROC200_High_Density_conn1_2: J1 J2 R39 R40 R41 R42 R125 R126 R127 R156 R157 R158 R159 R160 R161 R162
component class PROC200_MII0_PHY2: C1 C2 C3 C4 C5 C6 C7 C8 C9 C10 C11 C12 C13 C14 C15 C16 C17 C18 C19 C20 C37 FB1 FB2 R1 R2 R3 R4 R5 R6 R7 R8 R9 R10 R11 R12 R13 R14 R15 R16 R17 R18 R19 R20 R21 R22 R23 R43 R44 TP5 TP6 TP7 U1 U8
component class PROC200_RGMII1_PHY1: C31 C38 C39 C40 C41 C42 C43 C44 C45 C46 C47 C48 C49 C50 C51 C52 C53 C54 C55 C56 C71 FB3 FB4 R57 R58 R59 R60 R61 R62 R63 R64 R65 R66 R67 R68 R69 R70 R71 R72 R73 R74 R75 R76 R77 R78 R86 R124 TP8 TP9 TP10 U2 U9
component class PROC200_HSEC_ADC: , C32 C33 C34 C35 C36 C62 C63 C64 C65 C66 C67 C68 C69 C70 C79 C80 C81 C82 C83 C84 C85 C86 C87 C94 R134 R135 R136 R137 R138 R139 R140 R141 R142 R143 R144 R145 R146 R147 R148 R149 R150 R151 R152 U3 U4 U5 U6 U7
component class PROC200_180pin_Edge_Connector: C25 C26 C27 C28 C29 C30 EC1 EC2 R154 R155 TP1 TP2 TP3 TP4 TP18 TP19 TP25
component class PROC200_EVM_Hardware: FID1 FID2 FID3 FID4 FID5 FID6 LBL1 Logo1 Logo2 Logo3 Logo4 MH1 MH2 MH3 MH4 ZZ1 ZZ2 ZZ3 ZZ4
differential pair PMIC_COMP2: +PMIC_COMP2_IN+ -PMIC_COMP2_IN-
differential pair PMIC_COMP1: +PMIC_COMP1_IN+ -PMIC_COMP1_IN-
differential pair USBMICROAB: +USBMICROAB_DP -USBMICROAB_DM
differential pair AM26x_USB0: +AM26x_USB0_DP -AM26x_USB0_DM
differential pair AM26x_ADC2_AIN_2_3: +AM26x_ADC2_AIN2_P -AM26x_ADC2_AIN3_N
differential pair AM26x_ADC2_AIN_0_1: +AM26x_ADC2_AIN0_P -AM26x_ADC2_AIN1_N
differential pair AM26x_ADC1_AIN_2_3: +AM26x_ADC1_AIN2_P -AM26x_ADC1_AIN3_N
differential pair AM26x_ADC1_AIN_0_1: +AM26x_ADC1_AIN0_P -AM26x_ADC1_AIN1_N
differential pair AM26x_ADC0_AIN_4_5: +AM26x_ADC0_AIN4_P -AM26x_ADC0_AIN5_N
differential pair AM26x_ADC0_AIN_2_3: +AM26x_ADC0_AIN2_P -AM26x_ADC0_AIN3_N
differential pair HSEC_ADC2_AIN_2_3: +HSEC_ADC2_AIN2_P -HSEC_ADC2_AIN3_N
differential pair HSEC_ADC2_AIN_0_1: +HSEC_ADC2_AIN0_P -HSEC_ADC2_AIN1_N
differential pair HSEC_ADC1_AIN_2_3: +HSEC_ADC1_AIN2_P -HSEC_ADC1_AIN3_N
differential pair HSEC_ADC1_AIN_0_1: +HSEC_ADC1_AIN0_P -HSEC_ADC1_AIN1_N
differential pair HSEC_ADC0_AIN_4_5: +HSEC_ADC0_AIN4_P -HSEC_ADC0_AIN5_N
differential pair HSEC_ADC0_AIN_2_3: +HSEC_ADC0_AIN2_P -HSEC_ADC0_AIN3_N
differential pair RJ45_ETH2_D3: +RJ45_ETH2_D3_P -RJ45_ETH2_D3_N
differential pair RJ45_ETH2_D2: +RJ45_ETH2_D2_P -RJ45_ETH2_D2_N
differential pair RJ45_ETH2_D1: +RJ45_ETH2_D1_P -RJ45_ETH2_D1_N
differential pair RJ45_ETH2_D0: +RJ45_ETH2_D0_P -RJ45_ETH2_D0_N
differential pair RJ45_ETH1_D3: +RJ45_ETH1_D3_P -RJ45_ETH1_D3_N
differential pair RJ45_ETH1_D2: +RJ45_ETH1_D2_P -RJ45_ETH1_D2_N
differential pair RJ45_ETH1_D1: +RJ45_ETH1_D1_P -RJ45_ETH1_D1_N
differential pair RJ45_ETH1_D0: +RJ45_ETH1_D0_P -RJ45_ETH1_D0_N

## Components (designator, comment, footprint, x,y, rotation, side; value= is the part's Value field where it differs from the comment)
C1 "GRM188C81C106MA73D" 0603 2945.8,720.94 r90 bottom value=10uF
C2 "GCM155R71E103KA37D" 0402 2879.3,725.86 r270 bottom value=0.01uF
C3 "GRM155R71E104KE14D" 0402 3021.23,1035.59 r0 top value=0.1uF
C4 "GRM155C81E105KE11D" FP-GRM155C81E105KE11D_0402-MFG 2722.6,1253.62 r90 bottom value=1µF
C5 "GRM155R71E104KE14D" 0402 2722.6,1261.49 r90 top value=0.1uF
C6 "GRM155C81E105KE11D" FP-GRM155C81E105KE11D_0402-MFG 2557.76,1050.91 r180 bottom value=1µF
C7 "GRM155R71E104KE14D" 0402 2549.91,1050.93 r180 top value=0.1uF
C8 "GRM155C81E105KE11D" FP-GRM155C81E105KE11D_0402-MFG 3019.35,1035.59 r0 bottom value=1µF
C9 "GRM188C81C106MA73D" 0603 2945.8,720.94 r90 top value=10uF
C10 "GCM155R71E103KA37D" 0402 3009.3,728.82 r270 top value=0.01uF
C11 "GRM155C81E105KE11D" FP-GRM155C81E105KE11D_0402-MFG 3019.35,976.53 r0 bottom value=1µF
C12 "GRM155R71E104KE14D" 0402 3021.23,976.53 r0 top value=0.1uF
C13 "GRM155C81E105KE11D" FP-GRM155C81E105KE11D_0402-MFG 3019.35,1094.64 r0 bottom value=1µF
C14 "GRM155R71E104KE14D" 0402 3021.23,1094.64 r0 top value=0.1uF
C15 "GRM188C81C106MA73D" 0603 2662.36,758.03 r90 bottom value=10uF
C16 "GCM155R71E103KA37D" 0402 2720.49,765.9 r270 bottom value=0.01uF
C17 "GRM155C81E105KE11D" FP-GRM155C81E105KE11D_0402-MFG 2557.81,1000.55 r180 bottom value=1µF
C18 "GRM155R71E104KE14D" 0402 2549.94,1000.55 r180 top value=0.1uF
C19 "GRM155C81E105KE11D" FP-GRM155C81E105KE11D_0402-MFG 2801.32,797.89 r270 bottom value=1µF
C20 "GRM155R71E104KE14D" 0402 2801.32,790.01 r270 top value=0.1uF
C21 "GRM188C81C106MA73D" 0603 23.23,911.12 r90 bottom value=10uF
C22 "GRM155R71E104KE14D" 0402 79.23,915.06 r270 bottom value=0.1uF
C23 "GRM188C81C106MA73D" 0603 376.49,887.5 r90 bottom value=10uF
C24 "GRM155R71E104KE14D" 0402 320.49,899.31 r270 bottom value=0.1uF
C25 "GRM188C81C106MA73D" 0603 1601.5,-253 r0 top value=10uF
C26 "GRM155R71E104KE14D" 0402 1603.38,-306 r180 top value=0.1uF
C27 "GRM188C81C106MA73D" 0603 1987.66,-256.16 r180 top value=10uF
C28 "GRM155R71E104KE14D" 0402 1979.79,-312.16 r0 top value=0.1uF
C29 "GRM188C81C106MA73D" 0603 1858.71,-256.22 r0 top value=10uF
C30 "GRM155R71E104KE14D" 0402 1866.59,-312.16 r180 top value=0.1uF
C31 "GRM188C81C106MA73D" 0603 2945.8,1673.7 r90 bottom value=10uF
C32 "GRM155R71E104KE14D" 0402 24,-219.5 r180 top value=0.1uF
C33 "GRM155R71E104KE14D" 0402 263.83,-310.04 r0 top value=0.1uF
C34 "GRM155R71E104KE14D" 0402 506.81,-309.7 r180 bottom value=0.1uF
C35 "GRM155R71E104KE14D" 0402 699.09,-309.7 r180 bottom value=0.1uF
C36 "GRM155R71E104KE14D" 0402 310.85,-309.81 r180 bottom value=0.1uF
C37 "GRM155R71E104KE14D" 0402 2648.73,1689.97 r180 top value=0.1uF
C38 "GCM155R71E103KA37D" 0402 2879.3,1678.62 r270 bottom value=0.01uF
C39 "GRM155R71E104KE14D" 0402 3027.14,1988.11 r0 top value=0.1uF
C40 "GRM155C81E105KE11D" FP-GRM155C81E105KE11D_0402-MFG 2722.6,2206.37 r90 bottom value=1µF
C41 "GRM155R71E104KE14D" 0402 2722.6,2214.25 r90 top value=0.1uF
C42 "GRM155C81E105KE11D" FP-GRM155C81E105KE11D_0402-MFG 2557.76,2003.66 r180 bottom value=1µF
C43 "GRM155R71E104KE14D" 0402 2549.89,2003.66 r180 top value=0.1uF
C44 "GRM155C81E105KE11D" FP-GRM155C81E105KE11D_0402-MFG 3019.35,1988.11 r0 bottom value=1µF
C45 "GRM188C81C106MA73D" 0603 2945.8,1673.7 r90 top value=10uF
C46 "GCM155R71E103KA37D" 0402 3009.3,1681.57 r270 top value=0.01uF
C47 "GRM155C81E105KE11D" FP-GRM155C81E105KE11D_0402-MFG 3019.35,1929.27 r0 bottom value=1µF
C48 "GRM155R71E104KE14D" 0402 3027.14,1929.27 r0 top value=0.1uF
C49 "GRM155C81E105KE11D" FP-GRM155C81E105KE11D_0402-MFG 3019.35,2047.4 r0 bottom value=1µF
C50 "GRM155R71E104KE14D" 0402 3027.14,2047.4 r0 top value=0.1uF
C51 "GRM188C81C106MA73D" 0603 2662.36,1710.78 r90 bottom value=10uF
C52 "GCM155R71E103KA37D" 0402 2720.49,1718.66 r270 bottom value=0.01uF
C53 "GRM155C81E105KE11D" FP-GRM155C81E105KE11D_0402-MFG 2557.76,1953.35 r180 bottom value=1µF
C54 "GRM155R71E104KE14D" 0402 2549.89,1953.35 r180 top value=0.1uF
C55 "GRM155C81E105KE11D" FP-GRM155C81E105KE11D_0402-MFG 2801.32,1750.64 r270 bottom value=1µF
C56 "GRM155R71E104KE14D" 0402 2801.32,1742.77 r270 top value=0.1uF
C57 "GRM188C81C106MA73D" 0603 1441.93,2008.73 r90 bottom value=10uF
C58 "GRM155R71E104KE14D" 0402 1384.45,2016.6 r270 bottom value=0.1uF
C59 "GRM188C81C106MA73D" 0603 1447.82,2419.38 r270 bottom value=10uF
C60 "GRM155R71E104KE14D" 0402 1384.45,2411.51 r90 bottom value=0.1uF
C61 "GR442QR73D102KW01L" 1808 1606.15,2563.73 r0 bottom value=1000pF
C62 "GRM1555C1H331JA01D" 0402 386,-79.38 r270 bottom value=330pF
C63 "GRM1555C1H331JA01D" 0402 299.38,-79.38 r270 bottom value=330pF
C64 "GRM1555C1H331JA01D" 0402 472.61,-79.38 r270 bottom value=330pF
C65 "GRM1555C1H331JA01D" 0402 169.46,-79.38 r270 bottom value=330pF
C66 "GRM1555C1H331JA01D" 0402 559.22,-79.38 r270 bottom value=330pF
C67 "GRM1555C1H331JA01D" 0402 647.18,-79.38 r270 bottom value=330pF
C68 "GRM1555C1H331JA01D" 0402 733.8,-79.38 r270 bottom value=330pF
C69 "GRM1555C1H331JA01D" 0402 82.85,-79.38 r270 bottom value=330pF
C70 "GRM1555C1H331JA01D" 0402 820.41,-79.38 r270 bottom value=330pF
C71 "GRM155R71E104KE14D" 0402 2148.62,2386.55 r180 top value=0.1uF
C72 "GRM188C81C106MA73D" 0603 2911,413.48 r270 top value=10uF
C73 "GRM188R60J226MEA0D" 0603 2791.5,546.48 r180 top value=22uF
C74 "GRM188C81C106MA73D" 0603 3341.94,296.91 r90 top value=10uF
C75 "GCM155R71E103KA37D" 0402 3507.03,192.19 r180 top value=0.01uF
C76 "GRM155C81E105KE11D" FP-GRM155C81E105KE11D_0402-MFG 3595.75,328.4 r0 top value=1µF
C77 "GCM155R71E103KA37D" 0402 2911.03,413.48 r90 bottom value=0.01uF
C78 "GRM155C81E105KE11D" FP-GRM155C81E105KE11D_0402-MFG 4117.11,-255.26 r90 top value=1µF
C79 "GRM1555C1H331JA01D" 0402 342.69,-79.38 r270 bottom value=330pF
C80 "GRM1555C1H331JA01D" 0402 256.07,-79.38 r270 bottom value=330pF
C81 "GRM1555C1H331JA01D" 0402 429.3,-79.38 r270 bottom value=330pF
C82 "GRM1555C1H331JA01D" 0402 212.77,-79.38 r270 bottom value=330pF
C83 "GRM1555C1H331JA01D" 0402 515.92,-79.38 r270 bottom value=330pF
C84 "GRM1555C1H331JA01D" 0402 603.87,-79.38 r270 bottom value=330pF
C85 "GRM1555C1H331JA01D" 0402 690.49,-79.38 r270 bottom value=330pF
C86 "GRM1555C1H331JA01D" 0402 126.15,-79.38 r270 bottom value=330pF
C87 "GRM1555C1H331JA01D" 0402 777.1,-79.38 r270 bottom value=330pF
C88 "GCM155R71E103KA37D" 0402 4342.11,-275.26 r90 top value=0.01uF
C89 "GRM155R61E225KE11D" "FP-GRM155R61E225KE11D_0402 (1005 metric)-MFG" 3887.11,-255.26 r90 top value=2.2µF
C94 "GRM1555C1H331JA01D" 0402 863.72,-79.38 r270 bottom value=330pF
C97 "GRM155C81E105KE11D" FP-GRM155C81E105KE11D_0402-MFG 3175.61,407.89 r0 top value=1µF
C100 "GRM155C81E105KE11D" FP-GRM155C81E105KE11D_0402-MFG 3246.36,445.38 r270 top value=1µF
C102 "GRM188C81C106MA73D" 0603 3459,2441.54 r0 top value=10uF
C103 "GRM155R71E104KE14D" 0402 3459,2503.54 r180 top value=0.1uF
C104 "GRM188C81C106MA73D" 0603 3133.66,2502.97 r270 top value=10uF
C105 "GRM155R71E104KE14D" 0402 3077.66,2495.09 r270 top value=0.1uF
C108 "GR442QR73D102KW01L" 1808 3691.49,2034.32 r90 bottom value=1000pF
C109 "GRM155R71E104KE14D" 0402 2258.68,1027.17 r0 bottom value=0.1uF
C110 "GRM155R71E104KE14D" 0402 1928.26,869.69 r180 bottom value=0.1uF
C111 "GRM155R71E104KE14D" 0402 1951.88,1208.27 r90 bottom value=0.1uF
C112 "GRM155R71E104KE14D" 0402 1141.24,1229.76 r90 bottom value=0.1uF
C113 "GRM155R71E104KE14D" 0402 983.76,856.32 r270 bottom value=0.1uF
C114 "GRM155R71E104KE14D" 0402 826.28,1207.64 r90 bottom value=0.1uF
C115 "GRM155R71E104KE14D" 0402 1420.43,856.32 r270 bottom value=0.1uF
C116 "GRM155R71E104KE14D" 0402 1577.91,1229.76 r90 bottom value=0.1uF
C117 "GRM155R71E104KE14D" 0402 1262.94,1229.76 r90 bottom value=0.1uF
C118 "GRM155R71E104KE14D" 0402 1553.85,1664.99 r180 top value=0.1uF
C119 "GR442QR73D102KW01L" 1808 3505.89,982.92 r180 bottom value=1000pF
C120 "GR442QR73D102KW01L" 1808 3505.89,1910.14 r180 bottom value=1000pF
C121 "GRM155R71E104KE14D" 0402 487.49,941.93 r270 top value=0.1uF
D1 "SMBJ6.5CA" SMB-Bi 3426,2475 r0 bottom value=6.5V
EC1 "controlCARD-120HSEC_Edge" controlCARD-120HSEC_Edge 901.05,-622.81 r0 top
EC2 "controlCARD-180HSEC-60pinAddon_Edge" controlCARD-180HSEC-60pinAddon_Edge 3237.32,-617.46 r0 top
FB1 "BLM18EG101TN1D" FP-BLM18EG101TN1D_0603-MFG 3009.3,728.82 r90 bottom
FB2 "BLM18EG101TN1D" FP-BLM18EG101TN1D_0603-MFG 2879.3,725.86 r90 top
FB3 "BLM18EG101TN1D" FP-BLM18EG101TN1D_0603-MFG 3009.3,1681.57 r90 bottom
FB4 "BLM18EG101TN1D" FP-BLM18EG101TN1D_0603-MFG 2879.3,1678.62 r90 top
FB5 "BLM18EG101TN1D" FP-BLM18EG101TN1D_0603-MFG 3243.71,1608.19 r0 bottom
FB6 "BLM18EG101TN1D" FP-BLM18EG101TN1D_0603-MFG 3244.91,675.92 r0 bottom
FID1 "Fiducial" Fiducial10-20 -207,2562 r90 top
FID2 "Fiducial" Fiducial10-20 -240,-20 r90 top
FID3 "Fiducial" Fiducial10-20 3720,-300 r90 top
FID4 "Fiducial" Fiducial10-20 -207,2562 r90 bottom
FID5 "Fiducial" Fiducial10-20 -240,-20 r90 bottom
FID6 "Fiducial" Fiducial10-20 3720,-300 r90 bottom
J1 "QTH-060-01-L-D-A" SAMTEC_QTH-060-01-L-D-A 1034.98,323.39 r180 top locked
J2 "QTH-060-01-L-D-A" SAMTEC_QTH-060-01-L-D-A -50.02,1138.39 r270 top locked
J3 "QTH-060-01-L-D-A" SAMTEC_QTH-060-01-L-D-A 2114.98,1138.19 r90 top locked
J4 "TSW-108-08-G-D-RA-008" FP-TSW-108-08-G-D-RA-008_HDR15-MFG 716.91,2829.97 r0 top
J5 "DF40GB(1.5)-30DS-0.4V(58)" FP-DF40GB(1.5)-30DS-0.4V(58)_HDR30-MFG 199.86,1033.17 r90 bottom locked
J6 "DF40GB-48DP-0.4V(58)" FP-DF40GB-48DP-0.4V(58)_HDR48-MFG 1253.28,2222.53 r90 bottom
J7 "629105150921" FP-629105150921_CONN_PTH_USB_8MM0_5MM6-MFG 3733.08,2648.85 r90 top
J8 "TMM-105-01-T-D" FP-TMM-105-01-T-D_HDR10-MFG 91,2750.37 r0 top
J9 "LPJG16314A4NL" FP-LPJG16314A4NL_CONN_RJ45-MFG 3525.21,1978.49 r90 top
J10 "LPJG16314A4NL" FP-LPJG16314A4NL_CONN_RJ45-MFG 3525.21,1025.74 r90 top
L1 "DLW21SN900HQ2L" IND_DLW21S 3411,2636.05 r270 top
L2 "IHLP2020BZER1R0M01" IHLP-2020BZ 2602,461.48 r90 top value=1uH
LBL1 "THT-14-423-10" Label_650x200 3746,-1528 r180 top
Logo1 "CE Mark" CE_Mark_5mm 1205,245 r180 bottom
Logo2 "Texas Instruments" TI_Stacked_Overlay_Small 1790,1650 r180 bottom
Logo3 "FCC disclaimer" FCC_disclaimer -290,-2170 r270 bottom
Logo4 "WEEE logo" WEEE_Minimum 1180,-60 r180 bottom
MH1 "MTG_NoPads" MTG_159mil 1809.98,618.39 r0 top
MH2 "MTG_NoPads" MTG_159mil 49.98,2088.39 r0 top
MH3 "MTG_NoPads" MTG_159mil 2019.98,2088.39 r0 top
MH4 "MTG_NoPads" MTG_159mil 49.98,183.39 r0 top
Q1 "BSS138LT1G" FP-BSS138LT1G_SOT-23-3-MFG 2948.05,1494.31 r0 top
Q2 "BSS138LT1G" FP-BSS138LT1G_SOT-23-3-MFG 2800.6,1494.31 r0 top
Q3 "BSS138LT1G" FP-BSS138LT1G_SOT-23-3-MFG 3095.49,1494.31 r180 top
Q4 "BSS138LT1G" FP-BSS138LT1G_SOT-23-3-MFG 2948.05,1494.31 r180 bottom
Q5 "BSS138LT1G" FP-BSS138LT1G_SOT-23-3-MFG 2800.6,1494.31 r180 bottom
Q6 "BSS138LT1G" FP-BSS138LT1G_SOT-23-3-MFG 3095.49,1494.31 r0 bottom
R1 "ERJ-2GE0R00X" 0402 2429.12,1000.6 r0 bottom value=0
R2 "CRCW040211K0FKED" 0402 3035.49,890.44 r0 bottom value=11.0k
R3 "ERJ-2GE0R00X" 0402 2960.81,1223.58 r0 bottom value=0
R4 "ERJ-2GE0R00X" 0402 2429.12,1050.91 r0 bottom value=0
R5 "CRCW04022K20FKED" 0402 2791.95,1294.45 r90 bottom value=2.20k
R6 "CRCW04022K49FKED" 0402 2552.49,1156.13 r90 bottom value=2.49k
R7 "CRCW04022K49FKED" 0402 2551.36,1284.45 r90 bottom value=2.49k
R8 "CRCW04022K49FKED" 0402 3031.24,1294.45 r90 bottom value=2.49k
R9 "CRCW04022K49FKED" 0402 2984.58,1295.05 r90 bottom value=2.49k
R10 "CRCW04022K49FKED" 0402 2839.49,1294.45 r90 bottom value=2.49k
R11 "CRCW04022K49FKED" 0402 2623.14,1294.45 r90 bottom value=2.49k
R12 "CRCW04022K49FKED" 0402 2551.36,1441.62 r90 bottom value=2.49k
R13 "CRCW04022K49FKED" 0402 2623.14,1441.62 r90 bottom value=2.49k
R14 "CRCW04022K49FKED" 0402 2538.05,884.54 r180 bottom value=2.49k
R15 "CRCW04022K49FKED" 0402 2501.95,1156.13 r270 bottom value=2.49k
R16 "CRCW04022K49FKED" 0402 2501.95,1284.45 r270 bottom value=2.49k
R17 "CRCW04022K49FKED" 0402 3079.03,1294.45 r270 bottom value=2.49k
R18 "CRCW04022K49FKED" 0402 2937.65,1294.45 r270 bottom value=2.49k
R19 "CRCW04022K49FKED" 0402 2887.03,1294.45 r270 bottom value=2.49k
R20 "CRCW04022K49FKED" 0402 2672.24,1294.45 r270 bottom value=2.49k
R21 "CRCW04022K49FKED" 0402 2501.95,1441.62 r270 bottom value=2.49k
R22 "CRCW04022K49FKED" 0402 2672.24,1441.62 r270 bottom value=2.49k
R23 "CRCW04022K49FKED" 0402 2538.05,835.44 r0 bottom value=2.49k
R24 "ERJ-2GE0R00X" 0402 518.51,2018.13 r270 bottom value=0
R25 "ERJ-2GE0R00X" 0402 542.13,2041.75 r0 bottom value=0
R26 "ERJ-2GE0R00X" 0402 281.66,2018.13 r270 bottom value=0
R27 "ERJ-2GE0R00X" 0402 305.28,2041.75 r0 bottom value=0
R28 "ERJ-2GE0R00X" 0402 239.54,1583.63 r270 bottom value=0
R29 "ERJ-2GE0R00X" 0402 263.16,1607.25 r0 bottom value=0
R30 "ERJ-2GE0R00X" 0402 653,1826.45 r270 bottom value=0
R31 "ERJ-2GE0R00X" 0402 356.65,984.18 r0 bottom value=0
R32 "ERJ-2GE0R00X" 0402 676.62,1850.07 r0 bottom value=0
R33 "ERJ-2GE0R00X" 0402 354.02,1643.63 r270 bottom value=0
R34 "ERJ-2GE0R00X" 0402 377.65,1667.25 r0 bottom value=0
R35 "ERJ-2GE0R00X" 0402 438.51,1583.63 r270 bottom value=0
R36 "ERJ-2GE0R00X" 0402 462.13,1607.25 r0 bottom value=0
R37 "ERJ-2GE0R00X" 0402 538.51,1826.45 r270 bottom value=0
R38 "ERJ-2GE0R00X" 0402 562.13,1850.07 r0 bottom value=0
R39 "ERJ-2GE0R00X" 0402 1332.54,56.87 r90 top value=0
R40 "ERJ-2GE0R00X" 0402 1285.23,56.87 r90 top value=0
R41 "ERJ-2GE0R00X" 0402 1237.92,56.87 r90 top value=0
R42 "RC0402JR-0710KL" FP-RC0402JR-0710KL_0402-MFG 1477.89,548.68 r270 top value=10k
R43 "RC0402JR-0710KL" FP-RC0402JR-0710KL_0402-MFG 2428.04,1616.37 r0 top value=10k
R44 "RC0402JR-0710KL" FP-RC0402JR-0710KL_0402-MFG 2689.49,1561.25 r270 top value=10k
R45 "ERJ-2GE0R00X" 0402 553,1643.63 r270 bottom value=0
R46 "ERJ-2GE0R00X" 0402 576.62,1667.25 r0 bottom value=0
R47 "ERJ-2GE0R00X" 0402 424.02,1826.45 r270 bottom value=0
R48 "ERJ-2GE0R00X" 0402 447.65,1850.07 r0 bottom value=0
R49 "ERJ-2GE0R00X" 0402 155.05,1643.63 r270 bottom value=0
R50 "ERJ-2GE0R00X" 0402 178.67,1667.25 r0 bottom value=0
R51 "ERJ-2GE0R00X" 0402 400.09,2018.13 r270 bottom value=0
R52 "ERJ-2GE0R00X" 0402 423.71,2041.75 r0 bottom value=0
R53 "ERJ-2GE0R00X" 0402 633,2018.13 r270 bottom value=0
R54 "ERJ-2GE0R00X" 0402 656.62,2041.75 r0 bottom value=0
R55 "ERJ-2GE0R00X" 0402 309.54,1826.45 r270 bottom value=0
R56 "ERJ-2GE0R00X" 0402 333.16,1850.07 r0 bottom value=0
R57 "ERJ-2GE0R00X" 0402 2409.12,1953.35 r0 bottom value=0
R58 "CRCW040211K0FKED" 0402 3035.49,1843.19 r0 bottom value=11.0k
R59 "ERJ-2GE0R00X" 0402 2409.12,2003.66 r0 bottom value=0
R60 "CRCW04022K20FKED" 0402 2791.95,2247.2 r90 bottom value=2.20k
R61 "CRCW04022K49FKED" 0402 2409.11,2097.11 r180 bottom value=2.49k
R62 "CRCW04022K49FKED" 0402 2409.11,2145.38 r180 bottom value=2.49k
R63 "CRCW04022K49FKED" 0402 2623.14,2247.2 r90 bottom value=2.49k
R64 "CRCW04022K49FKED" 0402 3031.24,2247.2 r90 bottom value=2.49k
R65 "CRCW04022K49FKED" 0402 2839.49,2247.2 r90 bottom value=2.49k
R66 "CRCW04022K49FKED" 0402 2983.44,2247.2 r90 bottom value=2.49k
R67 "CRCW04022K49FKED" 0402 2538.05,1837.3 r180 bottom value=2.49k
R68 "CRCW04022K49FKED" 0402 2538.05,2145.38 r180 bottom value=2.49k
R69 "CRCW04022K49FKED" 0402 2538.05,2294.69 r180 bottom value=2.49k
R70 "CRCW04022K49FKED" 0402 2409.11,2048.97 r0 bottom value=2.49k
R71 "CRCW04022K49FKED" 0402 2409.11,2193.38 r0 bottom value=2.49k
R72 "CRCW04022K49FKED" 0402 2672.24,2247.2 r270 bottom value=2.49k
R73 "CRCW04022K49FKED" 0402 3079.03,2247.2 r270 bottom value=2.49k
R74 "CRCW04022K49FKED" 0402 2887.03,2247.2 r270 bottom value=2.49k
R75 "CRCW04022K49FKED" 0402 2935.65,2247.2 r270 bottom value=2.49k
R76 "CRCW04022K49FKED" 0402 2538.05,1788.19 r0 bottom value=2.49k
R77 "CRCW04022K49FKED" 0402 2538.05,2193.38 r0 bottom value=2.49k
R78 "CRCW04022K49FKED" 0402 2538.05,2246.69 r0 bottom value=2.49k
R79 "RC0402JR-0710KL" FP-RC0402JR-0710KL_0402-MFG 1424.45,2104.42 r180 bottom value=10k
R80 "RC0402JR-0710KL" FP-RC0402JR-0710KL_0402-MFG 1423.62,2283.91 r180 bottom value=10k
R81 "RC0402JR-0710KL" FP-RC0402JR-0710KL_0402-MFG 1424.45,2217.4 r0 bottom value=10k
R82 "RC0402JR-0710KL" FP-RC0402JR-0710KL_0402-MFG 1049.58,2423.63 r180 bottom value=10k
R83 "RC0402JR-0710KL" FP-RC0402JR-0710KL_0402-MFG 1049.58,2324.89 r180 bottom value=10k
R84 "ERJ-6GEY0R00V" 0805_HV 1606.2,2682.73 r180 bottom value=0
R85 "ERJ-2GE0R00X" 0402 3093.71,462.82 r90 top value=0
R86 "RC0402JR-0710KL" FP-RC0402JR-0710KL_0402-MFG 1861.23,2386.55 r0 top value=10k
R87 "ERJ-2GE0R00X" 0402 2709.63,301.15 r90 bottom value=0
R88 "RC0402JR-0710KL" FP-RC0402JR-0710KL_0402-MFG 2812.14,2396.67 r0 top value=10k
R89 "RC0402JR-0710KL" FP-RC0402JR-0710KL_0402-MFG 3088.19,2396.67 r0 top value=10k
R90 "ERJ-2GE0R00X" 0402 3276.81,2688.68 r90 top value=0
R91 "RC0402JR-0710KL" FP-RC0402JR-0710KL_0402-MFG 3170,2768.31 r90 top value=10k
R92 "ERJ-2GE0R00X" 0402 3325.81,2636.05 r90 top value=0
R93 "ERJ-2GE0R00X" 0402 3276.81,2583.43 r270 top value=0
R94 "ERJ-6GEY0R00V" 0805_HV 3585.95,2052.47 r270 bottom value=0
R95 "RC0402JR-0710KL" FP-RC0402JR-0710KL_0402-MFG 1947.94,1027.17 r270 bottom value=10k
R96 "RC0402JR-0710KL" FP-RC0402JR-0710KL_0402-MFG 964.08,1205.83 r270 bottom value=10k
R97 "RC0402JR-0710KL" FP-RC0402JR-0710KL_0402-MFG 2024.41,2691 r0 top value=10k
R98 "RC0402JR-0710KL" FP-RC0402JR-0710KL_0402-MFG 1578.02,2691 r180 top value=10k
R99 "RC0402JR-0710KL" FP-RC0402JR-0710KL_0402-MFG 1400.74,1229.76 r270 bottom value=10k
R100 "CRCW04022K20FKED" 0402 1692.09,1494.49 r0 top value=2.20k
R101 "CRCW04022K20FKED" 0402 1283.85,1553.49 r180 top value=2.20k
R102 "CRCW04022K20FKED" 0402 1692.09,1552.28 r0 top value=2.20k
R103 "CRCW04022K20FKED" 0402 1283.85,1603.99 r180 top value=2.20k
R104 "CRCW04022K20FKED" 0402 1283.85,1510.19 r180 top value=2.20k
R105 "CRCW04022K20FKED" 0402 1692.09,1437.99 r0 top value=2.20k
R106 "RC0402JR-0710KL" FP-RC0402JR-0710KL_0402-MFG 1283.85,1661 r180 top value=10k
R107 "RC0402JR-0710KL" FP-RC0402JR-0710KL_0402-MFG 1670.67,1623.81 r0 top value=10k
R108 "CRCW0402220RJNED" 0402 2962.81,1405.81 r180 top value=220
R109 "ERJ-2GE0R00X" 0402 2933.28,1582.81 r180 top value=0
R110 "CRCW0402220RJNED" 0402 2815.37,1405.81 r180 top value=220
R111 "ERJ-2GE0R00X" 0402 2785.84,1582.81 r180 top value=0
R112 "CRCW0402220RJNED" 0402 3596.67,2349.67 r0 bottom value=220
R113 "ERJ-2GE0R00X" 0402 3120.49,1582.81 r0 top value=0
R114 "ERJ-6GEY0R00V" 0805_HV 3465.21,1088.92 r0 bottom value=0
R115 "CRCW0402220RJNED" 0402 2948.05,1582.44 r0 bottom value=220
R116 "ERJ-2GE0R00X" 0402 2948.05,1405.81 r0 bottom value=0
R117 "CRCW0402220RJNED" 0402 2800.6,1405.81 r0 bottom value=220
R118 "CRCW0402220RJNED" 0402 3596.67,1396.92 r0 bottom value=220
R119 "ERJ-2GE0R00X" 0402 2800.6,1582.81 r0 bottom value=0
R120 "ERJ-2GE0R00X" 0402 3080.72,1405.81 r180 bottom value=0
R121 "ERJ-6GEY0R00V" 0805_HV 3465.21,2017.19 r0 bottom value=0
R122 "RC0402JR-0710KL" FP-RC0402JR-0710KL_0402-MFG 486.93,660.21 r90 top value=10k
R123 "RC0402JR-0710KL" FP-RC0402JR-0710KL_0402-MFG 562.29,941.93 r270 top value=10k
R124 "RC0402JR-0710KL" FP-RC0402JR-0710KL_0402-MFG 2128.6,2311.75 r180 top value=10k
R125 "ERJ-2GE0R00X" 0402 1190.61,56.87 r90 top value=0
R126 "ERJ-2GE0R00X" 0402 1143.31,56.87 r90 top value=0
R127 "ERJ-2GE0R00X" 0402 1096,56.87 r90 top value=0
R128 "RC0402JR-0710KL" FP-RC0402JR-0710KL_0402-MFG 2750.69,493.74 r180 bottom value=10k
R129 "CRCW04024K70JNED" 0402 2754.62,550.74 r0 bottom value=4.7k
R130 "ERJ-2RKF1001X" 0402 2281.1,2691 r180 top value=1.00k
R131 "ERJ-2RKF1001X" 0402 1874.09,2691 r180 top value=1.00k
R132 "ERJ-2GE0R00X" 0402 3621.56,271 r0 top value=0
R133 "RC0402JR-0710KL" FP-RC0402JR-0710KL_0402-MFG 2652.63,298.83 r90 bottom value=10k
R134 "ERJ-2GE0R00X" 0402 342.69,-79.38 r270 top value=0
R135 "ERJ-2GE0R00X" 0402 386,-79.38 r270 top value=0
R136 "ERJ-2GE0R00X" 0402 256.07,-79.38 r270 top value=0
R137 "ERJ-2GE0R00X" 0402 299.38,-79.38 r270 top value=0
R138 "ERJ-2GE0R00X" 0402 429.3,-79.38 r270 top value=0
R139 "ERJ-2GE0R00X" 0402 472.61,-79.38 r270 top value=0
R140 "ERJ-2GE0R00X" 0402 212.77,-79.38 r270 top value=0
R141 "ERJ-2GE0R00X" 0402 169.46,-79.38 r270 top value=0
R142 "ERJ-2GE0R00X" 0402 515.92,-79.38 r270 top value=0
R143 "ERJ-2GE0R00X" 0402 559.22,-79.38 r270 top value=0
R144 "ERJ-2GE0R00X" 0402 603.87,-79.38 r270 top value=0
R145 "ERJ-2GE0R00X" 0402 647.18,-79.38 r270 top value=0
R146 "ERJ-2GE0R00X" 0402 690.49,-79.38 r270 top value=0
R147 "ERJ-2GE0R00X" 0402 733.8,-79.38 r270 top value=0
R148 "ERJ-2GE0R00X" 0402 126.15,-79.38 r270 top value=0
R149 "ERJ-2GE0R00X" 0402 82.85,-79.38 r270 top value=0
R150 "ERJ-2GE0R00X" 0402 777.1,-79.38 r270 top value=0
R151 "ERJ-2GE0R00X" 0402 820.41,-79.38 r270 top value=0
R152 "ERJ-2GE0R00X" 0402 863.72,-79.38 r270 top value=0
R153 "ERJ-2GE0R00X" 0402 1627.09,1229.76 r90 bottom value=0
R154 "CRCW04029K10JNED" 0402 907.02,-79.38 r90 top value=9.1k
R155 "CRCW040211K0FKED" 0402 907.02,-79.38 r270 bottom value=11.0k
R156 "ERJ-2GE0R00X" 0402 1502.25,33.46 r0 top value=0
R157 "ERJ-2GE0R00X" 0402 1502.25,78.82 r0 top value=0
R158 "ERJ-2GE0R00X" 0402 1570.71,596.66 r270 top value=0
R159 "ERJ-2GE0R00X" 0402 273.05,1704.65 r180 top value=0
R160 "ERJ-2GE0R00X" 0402 273.05,1750.66 r180 top value=0
R161 "ERJ-2GE0R00X" 0402 1524.04,596.66 r270 top value=0
R162 "ERJ-2GE0R00X" 0402 273.05,1607.25 r180 top value=0
SW1 "TDA01H0SB1R" FP-TDA01H0SB1R_SMT_SW_2MM40_6MM20-MFG 2561.74,2788 r0 top
SW2 "TDA01H0SB1R" FP-TDA01H0SB1R_SMT_SW_2MM40_6MM20-MFG 2941,2788 r180 top
SW3 "TDA01H0SB1R" FP-TDA01H0SB1R_SMT_SW_2MM40_6MM20-MFG 2154.72,2788 r0 top
SW4 "TDA01H0SB1R" FP-TDA01H0SB1R_SMT_SW_2MM40_6MM20-MFG 1747.71,2788 r0 top
TP1 "CMP-0078143-4" TP_25MIL-SMT 1633,-167.5 r0 top
TP2 "CMP-0078143-4" TP_25MIL-SMT 1956.16,-123.78 r90 top
TP3 "CMP-0078143-4" TP_25MIL-SMT 1890.21,-159.78 r0 top
TP4 "CMP-0078143-4" TP_25MIL-SMT 1827.22,-159.78 r0 top
TP5 "TESTPOINT" TP_25MIL-SMT 2946.49,837.44 r90 bottom
TP6 "TESTPOINT" TP_25MIL-SMT 3011.87,837.44 r90 bottom
TP7 "TESTPOINT" TP_25MIL-SMT 2722.95,1339.92 r90 bottom
TP8 "TESTPOINT" TP_25MIL-SMT 2946.49,1790.19 r90 bottom
TP9 "TESTPOINT" TP_25MIL-SMT 3011.87,1790.19 r180 bottom
TP10 "TESTPOINT" TP_25MIL-SMT 2722.95,2292.68 r90 bottom
TP11 "TESTPOINT" TP_25MIL-SMT 1758,2693 r180 top
TP12 "TESTPOINT" TP_25MIL-SMT 1500,2305 r0 bottom
TP13 "TESTPOINT" TP_25MIL-SMT 3138,358 r180 top
TP14 "TESTPOINT" TP_25MIL-SMT 3246.78,489.58 r0 top
TP15 "TESTPOINT" TP_25MIL-SMT 2262.98,1146.17 r180 bottom
TP16 "TESTPOINT" TP_25MIL-SMT 3658,2416 r90 bottom
TP17 "TESTPOINT" TP_25MIL-SMT 3236,2416 r90 bottom
TP18 "CMP-0078143-4" TP_25MIL-SMT 962,-55.76 r90 top
TP19 "5002" Keystone5002 2569,2658 r90 bottom
TP20 "TESTPOINT" TP_25MIL-SMT 2262.98,1196 r180 bottom
TP21 "TESTPOINT" TP_25MIL-SMT 3570,415 r90 top
TP22 "5002" Keystone5002 3453,438 r90 top
TP23 "5002" Keystone5002 1462,2736.73 r90 top
TP24 "TESTPOINT" TP_25MIL-SMT 4777.11,-240.26 r90 top
TP25 "CMP-0078143-4" TP_25MIL-SMT 3867.11,-510.26 r90 top
U1 "DP83869HMRGZT" RGZ0048B-MFG 2791.49,1025.75 r180 bottom
U2 "DP83869HMRGZT" RGZ0048B-MFG 2791.49,1978.51 r180 bottom
U3 "TPD4E001DPKR" DPK0006A 79,-298 r90 top
U4 "TPD4E001DPKR" DPK0006A 219.98,-238.06 r270 top
U5 "TPD4E001DPKR" DPK0006A 354.15,-238.06 r270 bottom
U6 "TPD4E001DPKR" DPK0006A 580.12,-238.06 r270 bottom
U7 "TPD4E001DPKR" DPK0006A 772.4,-238.06 r270 bottom
U8 "SN74AHC1G09DBVR" DBV0005A_N 2571.49,1578.97 r0 top
U9 "SN74AHC1G09DBVR" DBV0005A_N 1996.44,2349.15 r0 top
U10 "TPS62097RWKR" RWK0011B 2795.83,413.48 r270 top
U11 "TPS22918DBVR" DBV0006A-MFG 3479.47,291 r0 top
U12 "TLV75511PDQNR" DQN0004A-MFG 3177.86,471.89 r180 top
U13 "TPS73533DRVR" DRV0006A 4597.11,-275.26 r0 top
U14 "TPS2051BDBVR" DBV0005A_N 2954.03,2434.07 r0 top
U15 "TPD4E02B04DQAR" DQA0010A 3532.1,2665.58 r180 top
U16 "TS3DDR3812RUAR" RUA0042A-MFG 2114.98,1027.17 r0 bottom
U17 "TS3DDR3812RUAR" RUA0042A-MFG 983.76,1043.04 r270 bottom
U18 "TS3DDR3812RUAR" RUA0042A-MFG 1420.43,1043.04 r270 bottom
U19 "TMUX154EDGSR" DGS0010A-MFG 1489.02,1552.28 r0 top
U20 "SN74AHC1G09DBVR" DBV0005A_N 524.89,798.53 r90 top
ZZ1 "This Assembly Note is for PCB labels only" AssemblyNoteLabel -778.06,3336.69 r0 top locked
ZZ2 "These assemblies are ESD sensitive, ESD precautions shall be observed." AssemblyNote -778.06,3227.81 r0 top locked
ZZ3 "These assemblies must be clean and free from flux and all contaminants. Use of no clean flux is not acceptable." AssemblyNote -800,3880 r0 top locked
ZZ4 "These assemblies must comply with workmanship standards IPC-A-610 Class 2, unless otherwise specified." AssemblyNote -778.06,3050.69 r0 top locked

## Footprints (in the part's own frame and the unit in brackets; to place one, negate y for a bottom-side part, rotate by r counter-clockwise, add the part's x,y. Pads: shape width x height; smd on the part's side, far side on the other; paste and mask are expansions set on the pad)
0402 [mm] "0402 from SM-752 data"
  rect 0.8x0.6 smd: 1(-0.6,0) 2(0.6,0)
  silkscreen extent -1.22,-0.52 1.22,0.52, body extent -0.55,-0.3 0.55,0.3, height 0.6
0603 [mm] "0603 from SM-752 data"
  rect 1x0.95 smd: 1(-0.8,0) 2(0.8,0)
  silkscreen extent -1.52,-0.69 1.52,0.69, body extent -0.87,-0.47 0.87,0.47, height 1
0805_HV [mil] "0805 with 30mil clearance between pads"
  rect 50x63 smd: 1(-40,0) 2(40,0)
  silkscreen extent -74,-40 74,40, body extent -43,-29 43,29, height 57
1808 [mm] "Chip Capacitor, Body 4.6x2.0mm, IPC Medium Density"
  rect 1.4x2.3 smd: 1(-2.1,0) 2(2.1,0)
  silkscreen extent -3.1,-1.45 3.1,1.45, body extent -2.47,-1.2 2.47,1.2, height 2.03
AssemblyNote [mil] "Assembly Note"
AssemblyNoteLabel [mil] "Assembly Note for PCB Labels"
CE_Mark_5mm [mil] "Minimum text height for CE Mark"
  silkscreen extent -138,-98 138,98
controlCARD-120HSEC_Edge [mm] "Edge Connector, 0.8mm, 60x2, pad numbers do not match Samtec datasheet"
  rect 0.55x2.8 smd paste-2.5 mask+0: 1(-23.6,2.4) 3(-22.8,2.4) 5(-22,2.4) 7(-21.2,2.4) 9(-20.4,2.4) 11(-19.6,2.4) 13(-18.8,2.4) 15(-18,2.4) 17(-17.2,2.4) 19(-16.4,2.4) 21(-15.6,2.4) 23(-14.8,2.4) 25(-14,2.4) 27(-13.2,2.4) 29(-12.4,2.4) 31(-11.6,2.4) 33(-10.8,2.4) 35(-10,2.4) 37(-9.2,2.4) 39(-8.4,2.4) 41(-7.6,2.4) 43(-6.8,2.4) 45(-6,2.4) 47(-5.2,2.4) 49(-4.4,2.4) 51(-3.6,2.4) 53(-2.8,2.4) 55(-2,2.4) 57(2,2.4) 59(2.8,2.4) 61(3.6,2.4) 63(4.4,2.4) 65(5.2,2.4) 67(6,2.4) 69(6.8,2.4) 71(7.6,2.4) 73(8.4,2.4) 75(9.2,2.4) 77(10,2.4) 79(10.8,2.4) 81(11.6,2.4) 83(12.4,2.4) 85(13.2,2.4) 87(14,2.4) 89(14.8,2.4) 91(15.6,2.4) 93(16.4,2.4) 95(17.2,2.4) 97(18,2.4) 99(18.8,2.4) 101(19.6,2.4) 103(20.4,2.4) 105(21.2,2.4) 107(22,2.4) 109(22.8,2.4) 111(23.6,2.4) 113(24.4,2.4) 115(25.2,2.4) 117(26,2.4) 119(26.8,2.4)
  rect 0.55x2.8 smd far side paste-2.5 mask+0: 2(-23.6,2.4) 4(-22.8,2.4) 6(-22,2.4) 8(-21.2,2.4) 10(-20.4,2.4) 12(-19.6,2.4) 14(-18.8,2.4) 16(-18,2.4) 18(-17.2,2.4) 20(-16.4,2.4) 22(-15.6,2.4) 24(-14.8,2.4) 26(-14,2.4) 28(-13.2,2.4) 30(-12.4,2.4) 32(-11.6,2.4) 34(-10.8,2.4) 36(-10,2.4) 38(-9.2,2.4) 40(-8.4,2.4) 42(-7.6,2.4) 44(-6.8,2.4) 46(-6,2.4) 48(-5.2,2.4) 50(-4.4,2.4) 52(-3.6,2.4) 54(-2.8,2.4) 56(-2,2.4) 58(2,2.4) 60(2.8,2.4) 62(3.6,2.4) 64(4.4,2.4) 66(5.2,2.4) 68(6,2.4) 70(6.8,2.4) 72(7.6,2.4) 74(8.4,2.4) 76(9.2,2.4) 78(10,2.4) 80(10.8,2.4) 82(11.6,2.4) 84(12.4,2.4) 86(13.2,2.4) 88(14,2.4) 90(14.8,2.4) 92(15.6,2.4) 94(16.4,2.4) 96(17.2,2.4) 98(18,2.4) 100(18.8,2.4) 102(19.6,2.4) 104(20.4,2.4) 106(21.2,2.4) 108(22,2.4) 110(22.8,2.4) 112(23.6,2.4) 114(24.4,2.4) 116(25.2,2.4) 118(26,2.4) 120(26.8,2.4)
controlCARD-180HSEC-60pinAddon_Edge [mm] "Edge Connector, 0.8mm, 30x2, pad numbers do not match Samtec datasheet"
  rect 0.55x2.8 smd paste-2.5 mask+0: 121(-11.6,2.4) 123(-10.8,2.4) 125(-10,2.4) 127(-9.2,2.4) 129(-8.4,2.4) 131(-7.6,2.4) 133(-6.8,2.4) 135(-6,2.4) 137(-5.2,2.4) 139(-4.4,2.4) 141(-3.6,2.4) 143(-2.8,2.4) 145(-2,2.4) 147(-1.2,2.4) 149(-0.4,2.4) 151(0.4,2.4) 153(1.2,2.4) 155(2,2.4) 157(2.8,2.4) 159(3.6,2.4) 161(4.4,2.4) 163(5.2,2.4) 165(6,2.4) 167(6.8,2.4) 169(7.6,2.4) 171(8.4,2.4) 173(9.2,2.4) 175(10,2.4) 177(10.8,2.4) 179(11.6,2.4)
  rect 0.55x2.8 smd far side paste-2.5 mask+0: 122(-11.6,2.4) 124(-10.8,2.4) 126(-10,2.4) 128(-9.2,2.4) 130(-8.4,2.4) 132(-7.6,2.4) 134(-6.8,2.4) 136(-6,2.4) 138(-5.2,2.4) 140(-4.4,2.4) 142(-3.6,2.4) 144(-2.8,2.4) 146(-2,2.4) 148(-1.2,2.4) 150(-0.4,2.4) 152(0.4,2.4) 154(1.2,2.4) 156(2,2.4) 158(2.8,2.4) 160(3.6,2.4) 162(4.4,2.4) 164(5.2,2.4) 166(6,2.4) 168(6.8,2.4) 170(7.6,2.4) 172(8.4,2.4) 174(9.2,2.4) 176(10,2.4) 178(10.8,2.4) 180(11.6,2.4)
DBV0005A_N [mm] "SOT23, 5-Leads, Body 2.9x1.6mm, Pitch 0.95mm, Lead Span 2.8mm, IPC Medium Density"
  rrect17% 1x0.6 smd: 1(-1.375,0.95) 2(-1.375,0) 3(-1.375,-0.95) 4(1.375,-0.95) 5(1.375,0.95)
  silkscreen extent -1.63,-1.55 0.38,1.55, body extent -1.42,-1.46 1.42,1.46, height 1.09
